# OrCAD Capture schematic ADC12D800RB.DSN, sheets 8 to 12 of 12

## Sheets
8 PLL: size B; block B3
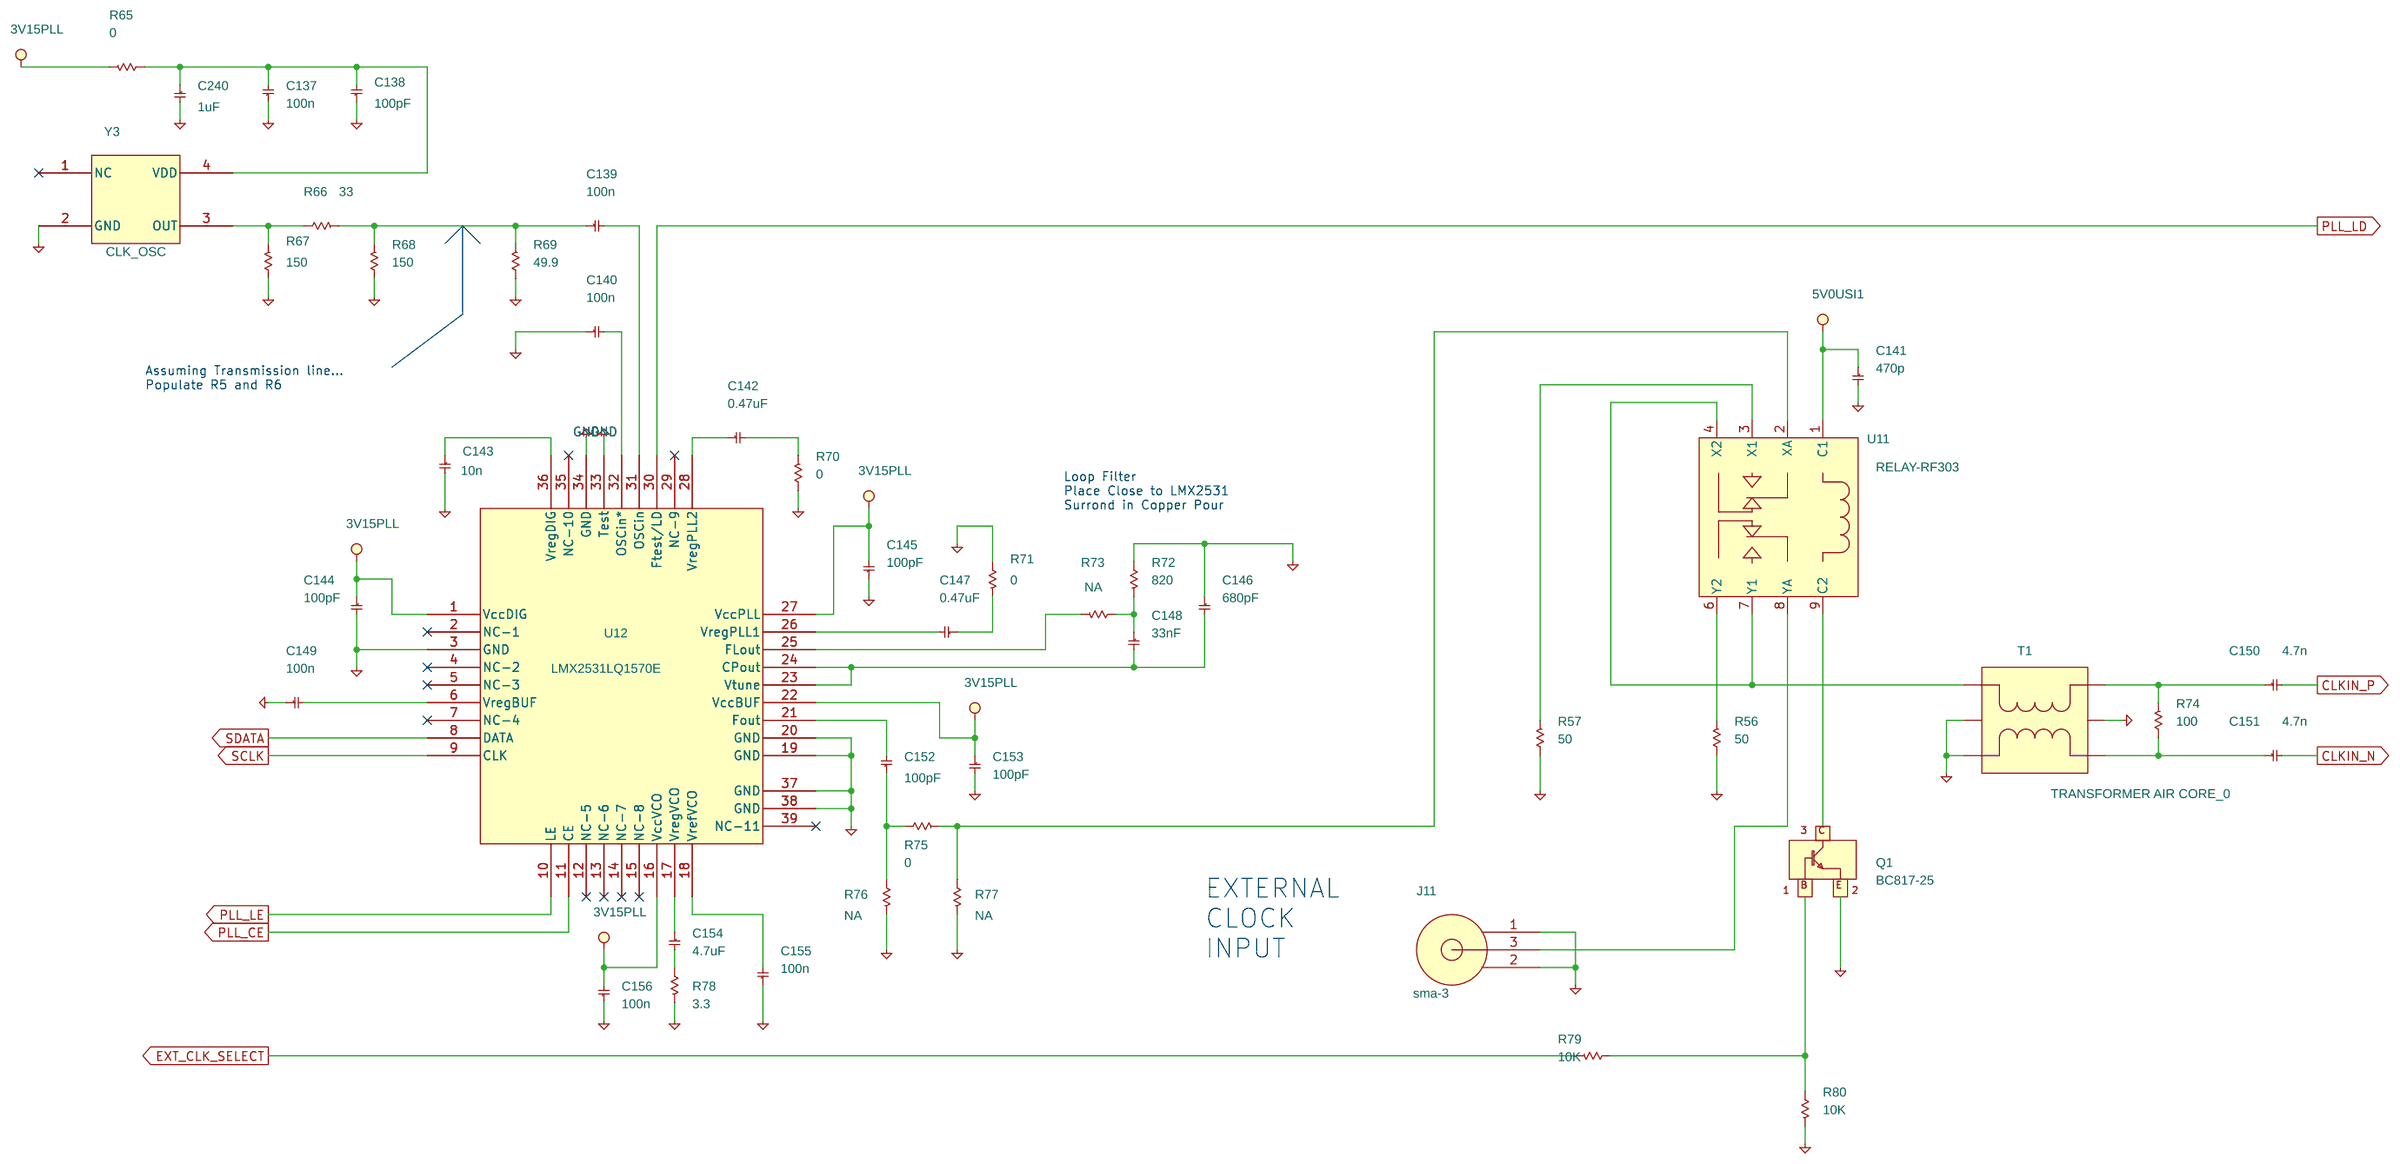
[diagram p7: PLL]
9 FPGA1: size C; block B7
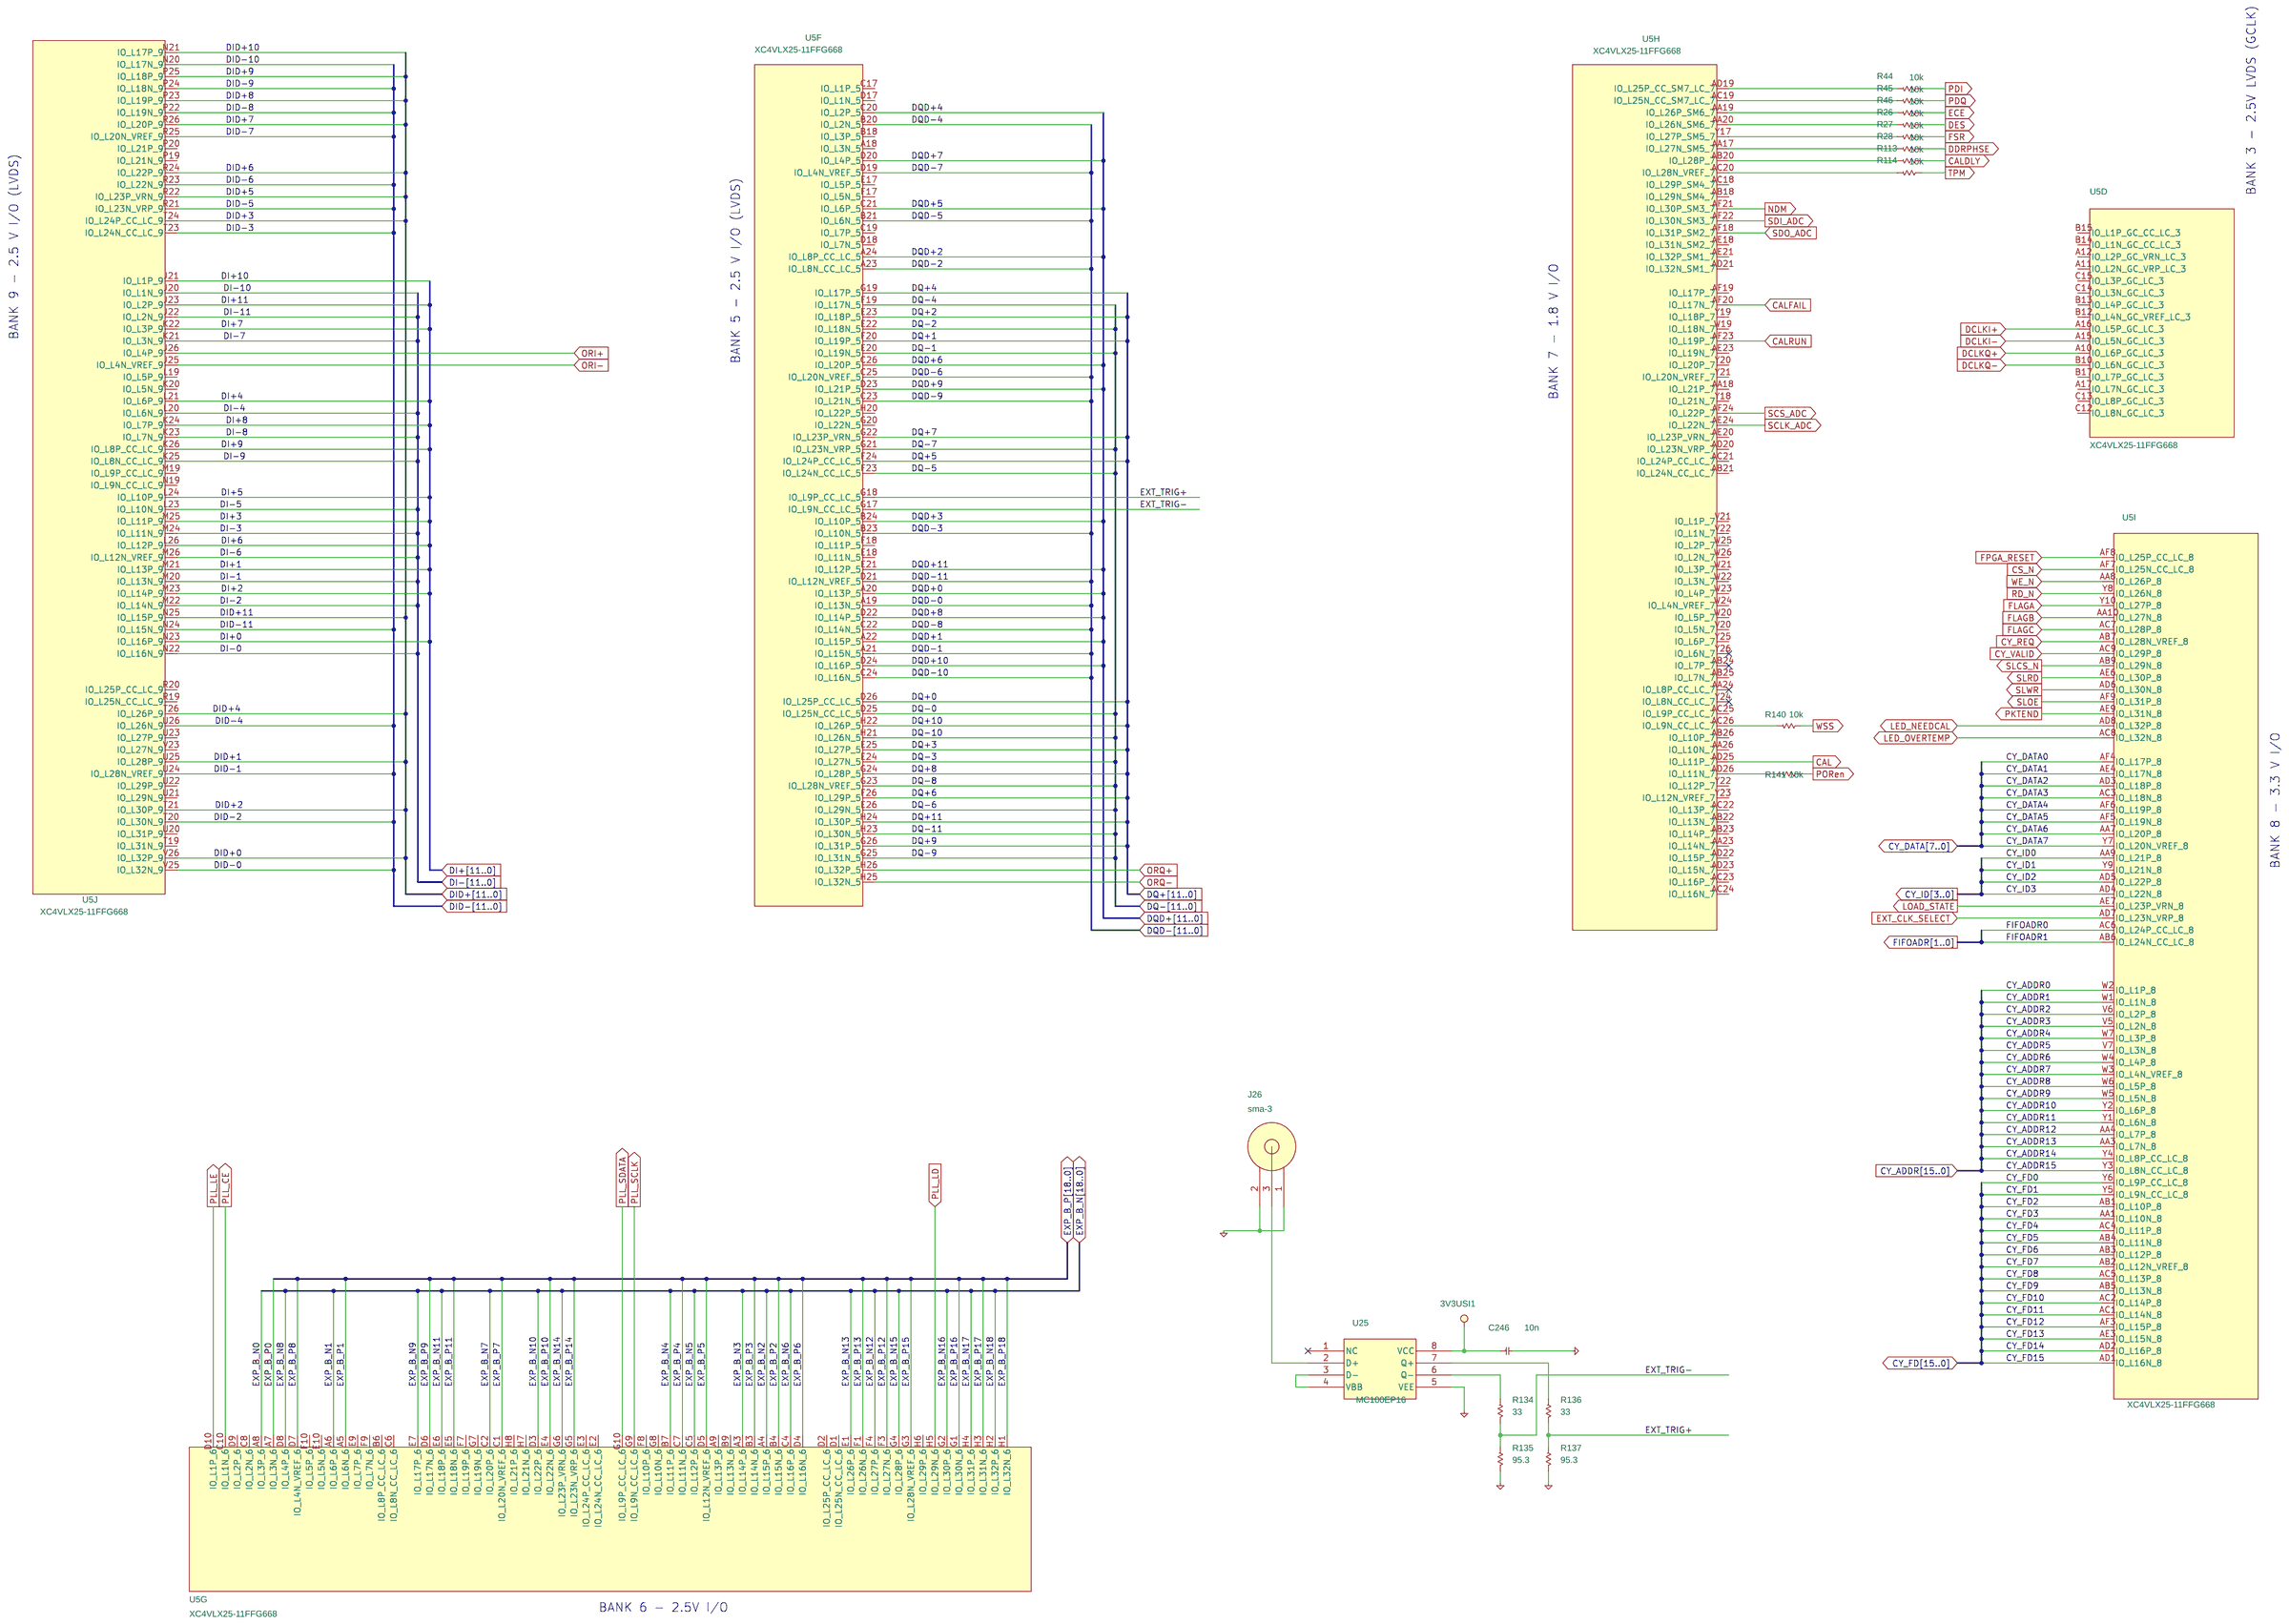
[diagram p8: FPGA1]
10 FPGA2: size C; block B7
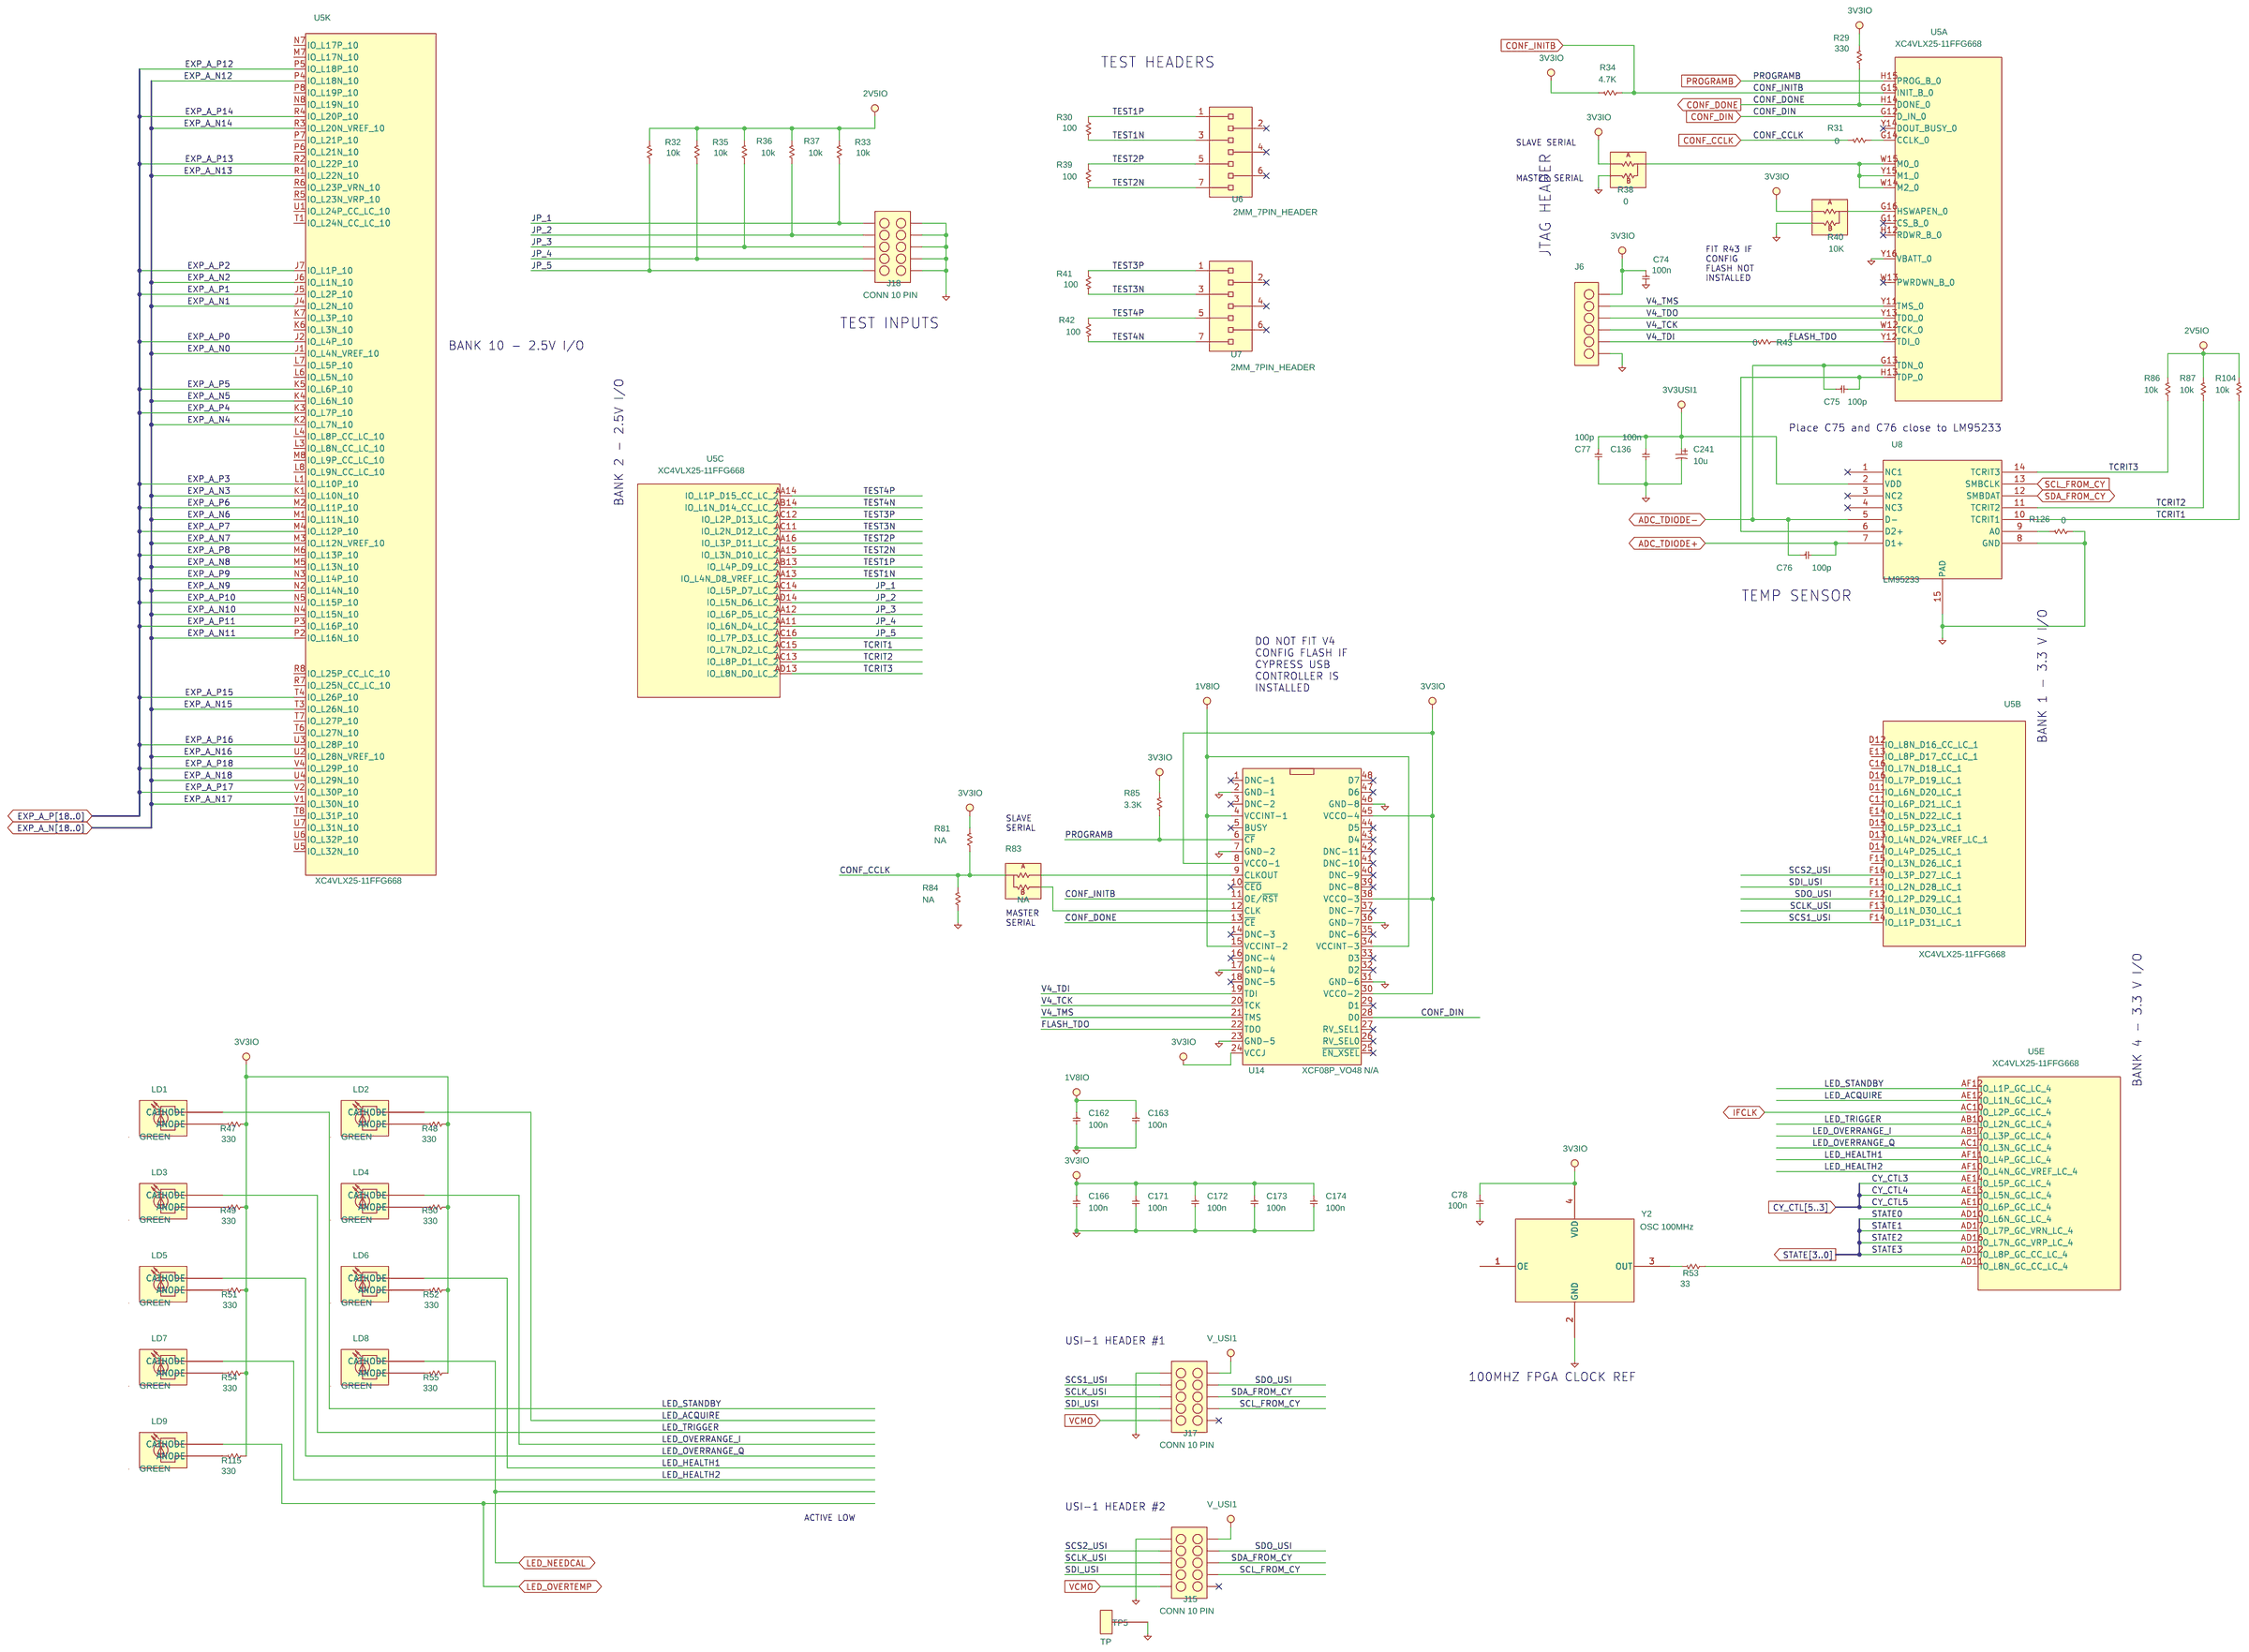
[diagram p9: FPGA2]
11 FPGA3: size C; block B7
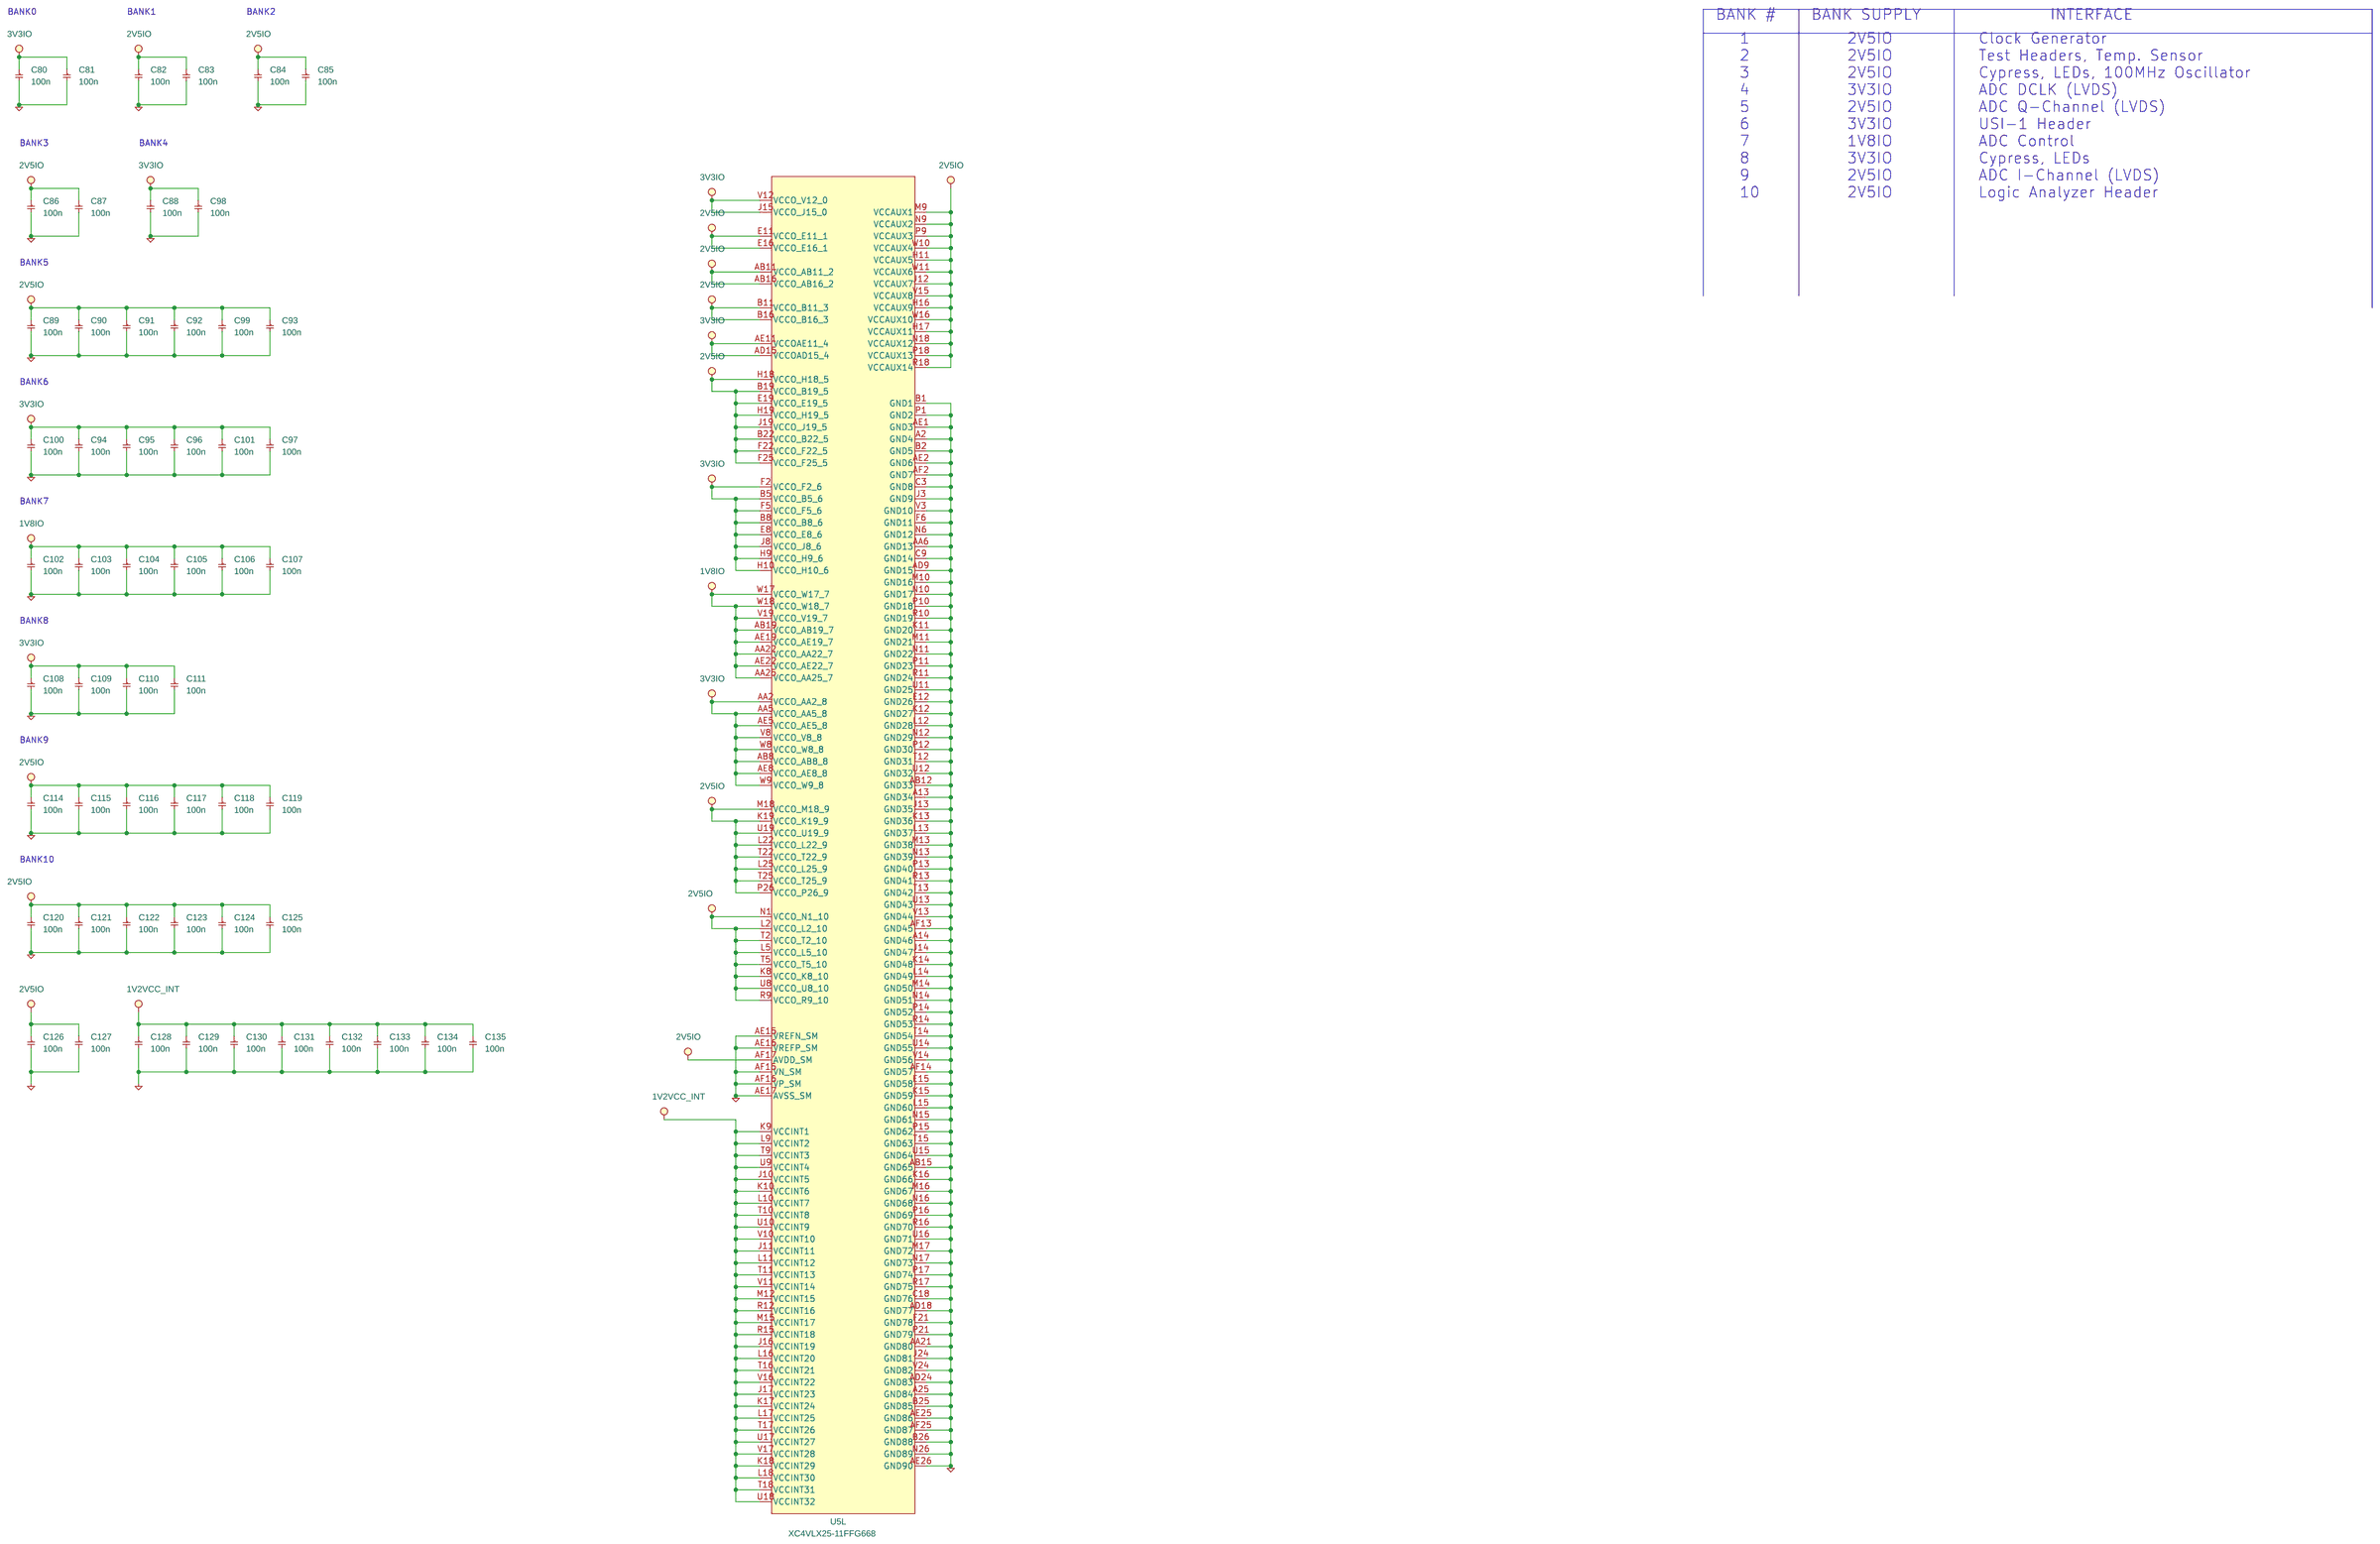
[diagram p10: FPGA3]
12 Front End: size C; block B6
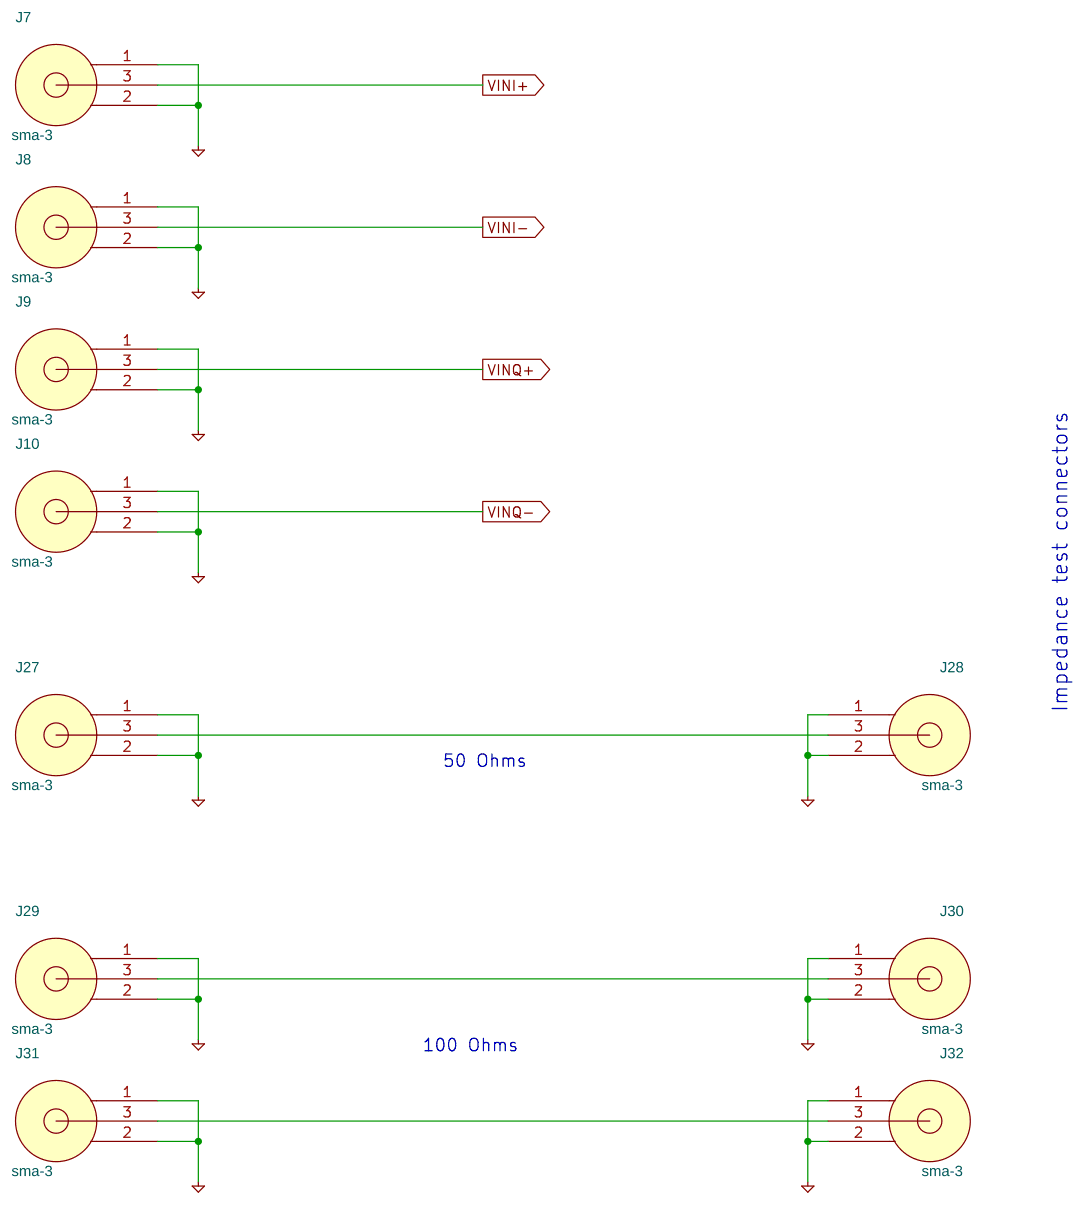
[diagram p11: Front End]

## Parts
sheet FPGA1
C246  10n  [c0402]
J26  sma-3  [RF_SMA_END_LAUNCH]
R26  10k  [r0603]
R27  10k  [r0603]
R28  10k  [r0603]
R44  10k  [r0603]
R45  10k  [r0603]
R46  10k  [r0603]
R113  10k  [r0603]
R114  10k  [r0603]
R134  33  [r0603]
R135  95.3  [r0603]
R136  33  [r0603]
R137  95.3  [r0603]
R140  10k  [r0603]
R141  10k  [r0603]
U25  MC100EP16  [TSSOP8_65M_WG4P9_L3]
sheet FPGA2
C74  100n  [c0603]
C75  100p  [c0402]
C76  100p  [c0402]
C77  100p  [c0402]
C78  100n  [c0603]
C136  100n  [c0603]
C162  100n  [c0603]
C163  100n  [c0603]
C166  100n  [c0603]
C171  100n  [c0603]
C172  100n  [c0603]
C173  100n  [c0603]
C174  100n  [c0603]
C241  10u  [c0805]
J6  CONN 6 PIN SINGLE ROW  [SHDR6X1]
J15  CONN 10 PIN  [th_10_hdr2x5_m_str_100]
J17  CONN 10 PIN  [th_10_hdr2x5_m_str_100]
J18  CONN 10 PIN  [th_10_hdr2x5_m_str_100]
LD1  GREEN  [r1206]
LD2  GREEN  [r1206]
LD3  GREEN  [r1206]
LD4  GREEN  [r1206]
LD5  GREEN  [r1206]
LD6  GREEN  [r1206]
LD7  GREEN  [r1206]
LD8  GREEN  [r1206]
LD9  GREEN  [r1206]
R29  330  [r0603]
R30  100  [r0603]
R31  0  [r0603]
R32  10k  [r0603]
R33  10k  [r0603]
R34  4.7K  [r0603]
R35  10k  [r0603]
R36  10k  [r0603]
R37  10k  [r0603]
R38  0  [0603_TRIPAD]
R39  100  [r0603]
R40  10K  [0603_TRIPAD]
R41  100  [r0603]
R42  100  [r0603]
R43  0  [r0603]
R47  330  [r0603]
R48  330  [r0603]
R49  330  [r0603]
R50  330  [r0603]
R51  330  [r0603]
R52  330  [r0603]
R53  33  [r0603]
R54  330  [r0603]
R55  330  [r0603]
R81  NA  [r0603]
R83  NA  [0603_TRIPAD]
R84  NA  [r0603]
R85  3.3K  [r0603]
R86  10k  [r0603]
R87  10k  [r0603]
R104  10k  [r0603]
R115  330  [r0603]
R126  0  [r0603]
TP5  TP  [tp40]
U5  XC4VLX25-11FFG668  [bga_668_27x27_1p0]  (sections A,B,C,D,E,F,G,H,I,J,K,L)
U6  2MM_7PIN_HEADER  [sm_7pin_ftr]
U7  2MM_7PIN_HEADER  [sm_7pin_ftr]
U8  LM95233  [LLP14_p5mm_4x4_ep]
U14  XCF08P_VO48 N/A  [TSSOP48_50M_WG20_L12]
Y2  OSC 100MHz  [osc_100m_5x7]
sheet FPGA3
C80  100n  [c0402]
C81  100n  [c0402]
C82  100n  [c0402]
C83  100n  [c0402]
C84  100n  [c0402]
C85  100n  [c0402]
C86  100n  [c0402]
C87  100n  [c0402]
C88  100n  [c0402]
C89  100n  [c0402]
C90  100n  [c0402]
C91  100n  [c0402]
C92  100n  [c0402]
C93  100n  [c0402]
C94  100n  [c0402]
C95  100n  [c0402]
C96  100n  [c0402]
C97  100n  [c0402]
C98  100n  [c0402]
C99  100n  [c0402]
C100  100n  [c0402]
C101  100n  [c0402]
C102  100n  [c0402]
C103  100n  [c0402]
C104  100n  [c0402]
C105  100n  [c0402]
C106  100n  [c0402]
C107  100n  [c0402]
C108  100n  [c0402]
C109  100n  [c0402]
C110  100n  [c0402]
C111  100n  [c0402]
C114  100n  [c0402]
C115  100n  [c0402]
C116  100n  [c0402]
C117  100n  [c0402]
C118  100n  [c0402]
C119  100n  [c0402]
C120  100n  [c0402]
C121  100n  [c0402]
C122  100n  [c0402]
C123  100n  [c0402]
C124  100n  [c0402]
C125  100n  [c0402]
C126  100n  [c0402]
C127  100n  [c0402]
C128  100n  [c0402]
C129  100n  [c0402]
C130  100n  [c0402]
C131  100n  [c0402]
C132  100n  [c0402]
C133  100n  [c0402]
C134  100n  [c0402]
C135  100n  [c0402]
sheet Front End
J7  sma-3  [RF_SMA_END_LAUNCH]
J8  sma-3  [RF_SMA_END_LAUNCH]
J9  sma-3  [RF_SMA_END_LAUNCH]
J10  sma-3  [RF_SMA_END_LAUNCH]
J27  sma-3  [RF_SMA_END_LAUNCH]
J28  sma-3  [RF_SMA_END_LAUNCH]
J29  sma-3  [RF_SMA_END_LAUNCH]
J30  sma-3  [RF_SMA_END_LAUNCH]
J31  sma-3  [RF_SMA_END_LAUNCH]
J32  sma-3  [RF_SMA_END_LAUNCH]
sheet PLL
C137  100n  [c0603]
C138  100pF  [c0603]
C139  100n  [c0603]
C140  100n  [c0603]
C141  470p  [c0603]
C142  0.47uF  [c0603]
C143  10n  [c0603]
C144  100pF  [c0603]
C145  100pF  [c0603]
C146  680pF  [c0603]
C147  0.47uF  [c0603]
C148  33nF  [c0603]
C149  100n  [c0603]
C150  4.7n  [c0402_no_ss]
C151  4.7n  [c0402_no_ss]
C152  100pF  [c0402_no_ss]
C153  100pF  [c0603]
C154  4.7uF  [c0603]
C155  100n  [c0603]
C156  100n  [c0603]
C240  1uF  [c0603]
J11  sma-3  [RF_SMA_END_LAUNCH]
Q1  BC817-25  [SOT-23]
R56  50  [r0402_no_ss]
R57  50  [r0402_no_ss]
R65  0  [r0603]
R66  33  [r0603]
R67  150  [r0603]
R68  150  [r0603]
R69  49.9  [r0603]
R70  0  [r0603]
R71  0  [r0603]
R72  820  [r0603]
R73  NA  [r0603]
R74  100  [r0402_no_ss]
R75  0  [r0402_no_ss]
R76  NA  [r0402_no_ss]
R77  NA  [r0402_no_ss]
R78  3.3  [r0603]
R79  10K  [r0603]
R80  10K  [r0603]
T1  TRANSFORMER AIR CORE_0  [soic6_026_wg049_L079]
U11  RELAY-RF303  [RELAY_RF303]
U12  LMX2531LQ1570E  [LLP39_p5mm_6x6]
Y3  CLK_OSC  [SOGP200_4_WGP280]

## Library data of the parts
C80-C111 C114-C135 C246 = C-NON-POL: Capacitor, SMT 0402, MLC, X5R, 10%, 10V; Distributor: Digikey; Distributor Part Number: PCC2146TR-ND; Manufacturer: Panasonic; Manufacturer Part Number: ECJ-0EB1A104K
J7-J11 J26-J32 = sma-3_0
R26-R28 R31 R44-R46 R65 R81 R84 R113 R114 R126 R140 R141 = RESISTOR_v2: RES 0 OHM 1/10W 5% 0603 SMD; Distributor: Digikey; Distributor Part Number: P0.0GTR-ND; Manufacturer: Panasonic; Manufacturer Part Number: ERJ-3GEY0R00V
R32 R33 R35-R37 R70 R71 R79 R80 R134-R137 = RESISTOR_v2: RES 10K OHM 1/10W 5% 0603 SMD; Distributor: Digikey; Distributor Part Number: P10KGTR-ND; Manufacturer: Panasonic; Manufacturer Part Number: ERJ-3GEYJ103V
U25 = MC10EP16: Distributor: Newark; Distributor Part Number: 45J0940; Manufacturer: On Semiconductor; Manufacturer Part Number: MC100EP16DTR2G
C74-C78 C136 C137 C139 C140 C149 C155 C156 C162 C163 C166 C171-C174 = C-NON-POL: Capacitor, SMT 0603, MLC, X7R, 10%, 16V; Distributor: Digikey; Distributor Part Number: PCC1762TR-ND; Manufacturer: Panasonic; Manufacturer Part Number: ECJ-1VB1C104K
C241 = C-POLARISED: CAP POL TDK 10UF X5R; Distributor: Digikey; Distributor Part Number: 445-1363-2-ND; Manufacturer: TDK; Manufacturer Part Number: C2012X5R0J1061M
J6 = CONN_6_PIN_SINGLE_ROW: HEADER 6X1 0.1" SP MALE STR; Distributor: Digikey; Distributor Part Number: S1012-36-ND; Manufacturer: Sullins; Manufacturer Part Number: PTC36SAAN
J15 J17 J18 = CONN_10_PIN_2mm_SMT_DUAL_ROW: CONN HEADER .100 DUAL STR 72POS; Distributor: Digikey; Distributor Part Number: S2012-36-ND; Manufacturer: Sullins; Manufacturer Part Number: PTC36DAAN
LD1-LD4 LD6 LD8 LD9 = LED_SNGLE_PANEL: LED 2X3MM 565NM GRN WTR CLR SMD; Distributor: Digikey; Distributor Part Number: 67-1357-1-ND; Manufacturer: Lumex; Manufacturer Part Number: SML-LX1206GC-TR
LD5 LD7 = LED_SNGLE_PANEL: LED 2X3MM 635NM RED WTR CLR SMD; Distributor: Digikey; Distributor Part Number: 67-1356-2-ND; Manufacturer: Lumex; Manufacturer Part Number: SML-LX1206IC-TR
R29 R47-R52 R54 R55 R115 = RESISTOR_v2: RES 330 OHM 1/10W 5% 0603 SMD; Distributor: Digikey; Distributor Part Number: P330GTR-ND; Manufacturer: Panasonic; Manufacturer Part Number: ERJ-3GEYJ331V
R30 R39 R41 R42 = RESISTOR_v2: RES 100 OHM 1/10W 5% 0603 SMD; Distributor: Digikey; Distributor Part Number: P100GTR-ND; Manufacturer: Panasonic; Manufacturer Part Number: ERJ-3GEYJ101V
R34 R43 = RESISTOR_v2: RES 4.7K OHM 1/10W 5% 0603 SMD; Distributor: Digikey; Distributor Part Number: P4.7KGTR-ND; Manufacturer: Panasonic; Manufacturer Part Number: ERJ-3GEYJ472V
R38 R83 = RESISTOR_TRIPAD: RES 0 OHM 1/10W 5% 0603 SMD; Distributor: Digikey; Distributor Part Number: P0.0GTR-ND; Manufacturer: Panasonic; Manufacturer Part Number: ERJ-3GEY0R00V
R40 = RESISTOR_TRIPAD: RES 10K OHM 1/10W 5% 0603 SMD; Distributor: Digikey; Distributor Part Number: P10KGTR-ND; Manufacturer: Panasonic; Manufacturer Part Number: ERJ-3GEYJ103V
R53 = RESISTOR_v2: RES 22.1K OHM 1/10W 1% 0603 SMD; Distributor: Digikey; Distributor Part Number: P22.1KHTR-ND; Manufacturer: Panasonic; Manufacturer Part Number: ERJ-3EKF2212V
R85-R87 R104 = RESISTOR_v2: RES 3.3K OHM 1/10W 5% 0603 SMD; Distributor: Digikey; Distributor Part Number: P3.3KGTR-ND; Manufacturer: Panasonic; Manufacturer Part Number: ERJ-3GEYJ332V
TP5 = TEST_POINT: TESTPOINT; Distributor: N/A; Distributor Part Number: N/A; Manufacturer: N/A; Manufacturer Part Number: N/A
U5 = XC4VLX25-11FFG668__3: FPGA VIRTEX-4 FG668 -11; Distributor: NuHorizons; Manufacturer: Xilinx
U6 U7 = 2MM_7PIN_HEADER: CONN HEADER 7POS SNGL 2MM SMD; Distributor: Digikey; Distributor Part Number: SAM1170-07-ND; Manufacturer: Samtec; Manufacturer Part Number: TMM-107-01-S-S-SM
U8 = LM95233
U14 = XCF08P_VO48_1: Xilinx Configuration Flash ROM (8Mb) JTAG; Manufacturer: Xilinx; Manufacturer Part Number: XCF08P VO48 C
Y2 = OSC-SM: OSC CLOCK 100.0000 MHZ 3.3V SMD; Distributor: Pletronics; Distributor Part Number: SM7745DSV-100.00M; Manufacturer: Pletronics; Manufacturer Part Number: SM7745DSV-100.00M
C138 C144 C145 C153 C154 = C-NON-POL: Capacitor, SMT 0603, MLC, NPO, 5%, 50V; Distributor: Digikey; Distributor Part Number: PCC101ACVTR-ND; Manufacturer: Panasonic; Manufacturer Part Number: ECJ-1VC1H101J
C141 = C-NON-POL: Capacitor, SMT 0603, MLC, NPO, 5%, 50V; Distributor: Digikey; Distributor Part Number: PCC2147CT-ND; Manufacturer: Panasonic; Manufacturer Part Number: ECJ-1VC1H471J
C142 C147 = C-NON-POL: Capacitor, SMT 0603, MLC, X7R, 10%, 16V; Distributor: Digikey; Distributor Part Number: 399-4922-2-ND; Manufacturer: Kemet; Manufacturer Part Number: C0603C474K4RACTU
C143 = C-NON-POL: Capacitor, SMT 0603, MLC, X7R, 10%, 16V; Distributor: Digikey; Distributor Part Number: PCC1750TR-ND; Manufacturer: Panasonic; Manufacturer Part Number: ECJ-1VB1C103K
C146 = C-NON-POL: Capacitor, SMT 0603, MLC, NPO, 5%, 50V; Distributor: Digikey; Distributor Part Number: PCC221ACVTR-ND; Manufacturer: Panasonic; Manufacturer Part Number: ECJ-1VC1H221J
C148 = C-NON-POL: Capacitor, SMT 0603, MLC, X7R, 10%, 16V; Distributor: Digikey; Distributor Part Number: 490-3292-1-ND; Manufacturer: MuRata; Manufacturer Part Number: GRM188R71C154KA01D
C150 C151 = C-NON-POL: Capacitor, SMT 0402, MLC, X7R, 10%, 25V; Distributor: Digikey; Distributor Part Number: PCC472BQTR-ND; Manufacturer: Panasonic; Manufacturer Part Number: ECJ-0EB1E472K
C152 = C-NON-POL: Capacitor, SMT 0402, MLC, X7R, 5%, 50V; Distributor: Digikey; Distributor Part Number: PCC101CQTR-ND; Manufacturer: Panasonic; Manufacturer Part Number: ECJ-0EC1H101J
C240 = C-NON-POL: Capacitor, SMT 0603, MLC, X5R, 10%, 16V; Distributor: Digikey; Distributor Part Number: PCC2224TR-ND; Manufacturer: Panasonic; Manufacturer Part Number: ECJ-1VB1C105K
Q1 = TRANSISTOR_NPN_BC817_SMD: TRANS NPN GP 500MA 45V SOT23; Distributor: Digikey; Distributor Part Number: BC817-25LT1OSCT-ND; Manufacturer: ON Semiconductor; Manufacturer Part Number: BC817-25LT1
R56 R57 R74 = RESISTOR_v2: RES 100 OHM 1/16W 5% 0402 SMD; Distributor: Digikey; Distributor Part Number: P100JTR-ND; Manufacturer: Panasonic; Manufacturer Part Number: ERJ-2GEJ101X
R66 R78 = RESISTOR_v2: RES 18 OHM 1/10W 5% 0603 SMD; Distributor: Digikey; Distributor Part Number: P18GTR-ND; Manufacturer: Panasonic; Manufacturer Part Number: ERJ-3GEYJ180V
R67 = RESISTOR_v2: RES 680 OHM 1/10W 5% 0603 SMD; Distributor: Digikey; Distributor Part Number: P680GTR-ND; Manufacturer: Panasonic; Manufacturer Part Number: ERJ-3GEYJ681V
R68 = RESISTOR_v2: RES 270 OHM 1/10W 5% 0603 SMD; Distributor: Digikey; Distributor Part Number: P270GTR-ND; Manufacturer: Panasonic; Manufacturer Part Number: ERJ-3GEYJ271V
R69 = RESISTOR_v2: RES 49.9 OHM 1/10W 1% 0603 SMD; Distributor: Digikey; Distributor Part Number: P49.9HCT-ND; Manufacturer: Panasonic; Manufacturer Part Number: ERJ-3EKF49R9V
R72 = RESISTOR_v2: RES 1K OHM 1/10W 5% 0603 SMD; Distributor: Digikey; Distributor Part Number: P1.0KGTR-ND; Manufacturer: Panasonic; Manufacturer Part Number: ERJ-3GEYJ102V
R73 = RESISTOR_v2: RES 2K7 OHM 1/10W 5% 0603 SMD; Distributor: Digikey; Distributor Part Number: P2.7KGTR-ND; Manufacturer: Panasonic; Manufacturer Part Number: ERJ-3GEYJ272V
R75-R77 = RESISTOR_v2: RES 0 OHM 1/16W 5% 0402 SMD; Distributor: Digikey; Distributor Part Number: P0.0JTR-ND; Manufacturer: Panasonic; Manufacturer Part Number: ERJ-2GE0R00X
T1 = TRANSFORMER_AIR_CORE_0: ANAREN XINGER FO-3 RF TRANSFORMER SMT; Manufacturer: Anaren; Manufacturer Part Number: FO-3
U11 = RELAY-RF303: RF RELAY DPDT; Distributor: Avnet; Manufacturer: Teledyne; Manufacturer Part Number: RF303-5
U12 = LMX2531LQ1500E
Y3 = Oscillator_4smd_0: Distributor: Pletronics; Distributor Part Number: SM7744HV-60.0M; Manufacturer: Pletronics; Manufacturer Part Number: SM7744HV-60.0M

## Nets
1V2VCC_INT: C128.1 C129.1 C130.1 C131.1 C132.1 C133.1 C134.1 C135.1 U5.J10(VCCINT5) U5.J11(VCCINT11) U5.J16(VCCINT19) U5.J17(VCCINT23) U5.K9(VCCINT1) U5.K10(VCCINT6) U5.K17(VCCINT24) U5.K18(VCCINT29) U5.L9(VCCINT2) U5.L10(VCCINT7) U5.L11(VCCINT12) U5.L16(VCCINT20) U5.L17(VCCINT25) U5.L18(VCCINT30) U5.M12(VCCINT15) U5.M15(VCCINT17) U5.R12(VCCINT16) U5.R15(VCCINT18) U5.T9(VCCINT3) U5.T10(VCCINT8) U5.T11(VCCINT13) U5.T16(VCCINT21) U5.T17(VCCINT26) U5.T18(VCCINT31) U5.U9(VCCINT4) U5.U10(VCCINT9) U5.U17(VCCINT27) U5.U18(VCCINT32) U5.V10(VCCINT10) U5.V11(VCCINT14) U5.V16(VCCINT22) U5.V17(VCCINT28) ; also on sheet 5
1V8IO: C102.1 C103.1 C104.1 C105.1 C106.1 C107.1 C162.1 C163.1 U5.AA22(VCCO_AA22_7) U5.AA25(VCCO_AA25_7) U5.AB19(VCCO_AB19_7) U5.AE19(VCCO_AE19_7) U5.AE22(VCCO_AE22_7) U5.V19(VCCO_V19_7) U5.W17(VCCO_W17_7) U5.W18(VCCO_W18_7) U14.4(VCCINT-1) U14.15(VCCINT-2) U14.34(VCCINT-3) ; also on sheet 3 5
2V5IO: C82.1 C83.1 C84.1 C85.1 C86.1 C87.1 C89.1 C90.1 C91.1 C92.1 C93.1 C99.1 C114.1 C115.1 C116.1 C117.1 C118.1 C119.1 C120.1 C121.1 C122.1 C123.1 C124.1 C125.1 C126.1 C127.1 R32.1 R33.1 R35.1 R36.1 R37.1 R86.1 R87.1 R104.1 U5.AB11(VCCO_AB11_2) U5.AB16(VCCO_AB16_2) U5.AF17(AVDD_SM) U5.B11(VCCO_B11_3) U5.B16(VCCO_B16_3) U5.B19(VCCO_B19_5) U5.B22(VCCO_B22_5) U5.E11(VCCO_E11_1) U5.E16(VCCO_E16_1) U5.E19(VCCO_E19_5) U5.F22(VCCO_F22_5) U5.F25(VCCO_F25_5) U5.H11(VCCAUX5) U5.H16(VCCAUX9) U5.H17(VCCAUX11) U5.H18(VCCO_H18_5) U5.H19(VCCO_H19_5) U5.J12(VCCAUX7) U5.J19(VCCO_J19_5) U5.K8(VCCO_K8_10) U5.K19(VCCO_K19_9) U5.L2(VCCO_L2_10) U5.L5(VCCO_L5_10) U5.L22(VCCO_L22_9) U5.L25(VCCO_L25_9) U5.M9(VCCAUX1) U5.M18(VCCO_M18_9) U5.N1(VCCO_N1_10) U5.N9(VCCAUX2) U5.N18(VCCAUX12) U5.P9(VCCAUX3) U5.P18(VCCAUX13) U5.P26(VCCO_P26_9) U5.R9(VCCO_R9_10) U5.R18(VCCAUX14) U5.T2(VCCO_T2_10) U5.T5(VCCO_T5_10) U5.T22(VCCO_T22_9) U5.T25(VCCO_T25_9) U5.U8(VCCO_U8_10) U5.U19(VCCO_U19_9) U5.V15(VCCAUX8) U5.W10(VCCAUX4) U5.W11(VCCAUX6) U5.W16(VCCAUX10) ; also on sheet 5
3V3IO: C74.1 C78.1 C80.1 C81.1 C88.1 C94.1 C95.1 C96.1 C97.1 C98.1 C100.1 C101.1 C108.1 C109.1 C110.1 C111.1 C166.1 C171.1 C172.1 C173.1 C174.1 J6.1 R29.1 R34.1 R38.1 R40.1 R47.2 R48.2 R49.2 R50.2 R51.2 R52.2 R54.2 R55.2 R81.1 R85.1 R115.2 U5.AA2(VCCO_AA2_8) U5.AA5(VCCO_AA5_8) U5.AB8(VCCO_AB8_8) U5.AD15(VCCOAD15_4) U5.AE5(VCCO_AE5_8) U5.AE8(VCCO_AE8_8) U5.AE11(VCCOAE11_4) U5.B5(VCCO_B5_6) U5.B8(VCCO_B8_6) U5.E8(VCCO_E8_6) U5.F2(VCCO_F2_6) U5.F5(VCCO_F5_6) U5.H9(VCCO_H9_6) U5.H10(VCCO_H10_6) U5.J8(VCCO_J8_6) U5.J15(VCCO_J15_0) U5.V8(VCCO_V8_8) U5.V12(VCCO_V12_0) U5.W8(VCCO_W8_8) U5.W9(VCCO_W9_8) U14.8(VCCO-1) U14.24(VCCJ) U14.30(VCCO-2) U14.38(VCCO-3) U14.45(VCCO-4) Y2.4(VDD) ; also on sheet 5
3V3USI1: C77.1 C136.1 C241.1(POS) C246.1 U8.2(VDD) U25.8(VCC) ; also on sheet 3 5
3V15PLL: C144.1 C145.2 C153.1 C156.2 R65.1 U12.1(VccDIG) U12.16(VccVCO) U12.22(VccBUF) U12.27(VccPLL) ; also on sheet 6
5V0USI1: C141.1 U11.1(C1) ; also on sheet 5
B7/V4_TCK: J6.4 U5.W12(TCK_0) U14.20(TCK)
B7/V4_TDI: J6.5 R43.1 U14.19(TDI)
B7/V4_TDO: J6.3 U5.Y13(TDO_0)
B7/V4_TMS: J6.2 U5.Y11(TMS_0) U14.21(TMS)
GND: C74.2 C77.2 C78.2 C80.2 C81.2 C82.2 C83.2 C84.2 C85.2 C86.2 C87.2 C88.2 C89.2 C90.2 C91.2 C92.2 C93.2 C94.2 C95.2 C96.2 C97.2 C98.2 C99.2 C100.2 C101.2 C102.2 C103.2 C104.2 C105.2 C106.2 C107.2 C108.2 C109.2 C110.2 C111.2 C114.2 C115.2 C116.2 C117.2 C118.2 C119.2 C120.2 C121.2 C122.2 C123.2 C124.2 C125.2 C126.2 C127.2 C128.2 C129.2 C130.2 C131.2 C132.2 C133.2 C134.2 C135.2 C136.2 C137.1 C138.1 C140.1 C141.2 C143.2 C144.2 C145.1 C146.1 C149.1 C153.2 C155.1 C156.1 C162.2 C163.2 C166.2 C171.2 C172.2 C173.2 C174.2 C240.2 C241.2(NEG) C246.2 J6.6 J7.1 J7.2 J8.1 J8.2 J9.1 J9.2 J10.1 J10.2 J11.1 J11.2 J15.1 J17.1 J18.2 J18.4 J18.6 J18.8 J18.10 J26.1 J26.2 J27.1 J27.2 J28.1 J28.2 J29.1 J29.2 J30.1 J30.2 J31.1 J31.2 J32.1 J32.2 Q1.2(EMITTER) R38.3 R40.3 R56.2 R57.2 R67.2 R68.2 R69.2 R70.2 R71.2 R72.2 R76.1 R77.1 R78.1 R80.1 R84.2 R126.2 R135.2 R137.2 T1.1 T1.3 T1.5 TP5.1 U5.A2(GND4) U5.A13(GND34) U5.A14(GND46) U5.A25(GND84) U5.AA6(GND13) U5.AA21(GND80) U5.AB12(GND33) U5.AB15(GND65) U5.AD9(GND15) U5.AD18(GND77) U5.AD24(GND83) U5.AE1(GND3) U5.AE2(GND6) U5.AE15(VREFN_SM) U5.AE16(VREFP_SM) U5.AE17(AVSS_SM) U5.AE25(GND86) U5.AE26(GND90) U5.AF2(GND7) U5.AF13(GND45) U5.AF14(GND57) U5.AF15(VN_SM) U5.AF16(VP_SM) U5.AF25(GND87) U5.B1(GND1) U5.B2(GND5) U5.B25(GND85) U5.B26(GND88) U5.C3(GND8) U5.C9(GND14) U5.C18(GND76) U5.E12(GND26) U5.E15(GND58) U5.F6(GND11) U5.F21(GND78) U5.J3(GND9) U5.J13(GND35) U5.J14(GND47) U5.J24(GND81) U5.K11(GND20) U5.K12(GND27) U5.K13(GND36) U5.K14(GND48) U5.K15(GND59) U5.K16(GND66) U5.L12(GND28) U5.L13(GND37) U5.L14(GND49) U5.L15(GND60) U5.M10(GND16) U5.M11(GND21) U5.M13(GND38) U5.M14(GND50) U5.M16(GND67) U5.M17(GND72) U5.N6(GND12) U5.N10(GND17) U5.N11(GND22) U5.N12(GND29) U5.N13(GND39) U5.N14(GND51) U5.N15(GND61) U5.N16(GND68) U5.N17(GND73) U5.N26(GND89) U5.P1(GND2) U5.P10(GND18) U5.P11(GND23) U5.P12(GND30) U5.P13(GND40) U5.P14(GND52) U5.P15(GND62) U5.P16(GND69) U5.P17(GND74) U5.P21(GND79) U5.R10(GND19) U5.R11(GND24) U5.R13(GND41) U5.R14(GND53) U5.R16(GND70) U5.R17(GND75) U5.T12(GND31) U5.T13(GND42) U5.T14(GND54) U5.T15(GND63) U5.U11(GND25) U5.U12(GND32) U5.U13(GND43) U5.U14(GND55) U5.U15(GND64) U5.U16(GND71) U5.V3(GND10) U5.V13(GND44) U5.V14(GND56) U5.V24(GND82) U5.Y16(VBATT_0) U8.8(GND) U8.15(PAD) U12.3(GND) U12.19(GND) U12.20(GND) U12.33(Test) U12.34(GND) U12.37(GND) U12.38(GND) U14.2(GND-1) U14.7(GND-2) U14.17(GND-4) U14.23(GND-5) U14.31(GND-6) U14.36(GND-7) U14.46(GND-8) U25.5(VEE) Y2.2(GND) Y3.2(GND) ; also on sheet 3 4 5 6 7
VINI+: J7.3 ; also on sheet 3
VINI-: J8.3 ; also on sheet 3
VINQ+: J9.3 ; also on sheet 3
VINQ-: J10.3 ; also on sheet 3
ADC_TDIODE+: C76.2 U8.7(D1+) ; also on sheet 3
ADC_TDIODE-: C75.1 C76.1 U5.G13(TDN_0) U8.5(D-) ; also on sheet 3
B7/EXT_TRIG+: R136.2 R137.1 U5.G18(IO_L9P_CC_LC_5)
B7/EXT_TRIG-: R134.2 R135.1 U5.G17(IO_L9N_CC_LC_5)
B7/FLASH_TDO: R43.2 U5.Y12(TDI_0) U14.22(TDO)
B7/JP_1: J18.1 R33.2 U5.AC14(IO_L5P_D7_LC_2)
B7/JP_2: J18.3 R37.2 U5.AD14(IO_L5N_D6_LC_2)
B7/JP_3: J18.5 R36.2 U5.AA12(IO_L6P_D5_LC_2)
B7/JP_4: J18.7 R35.2 U5.AA11(IO_L6N_D4_LC_2)
B7/JP_5: J18.9 R32.2 U5.AC16(IO_L7P_D3_LC_2)
B7/LED_ACQUIRE: LD2.2(CATHODE) U5.AE12(IO_L1N_GC_LC_4)
B7/LED_HEALTH1: LD6.2(CATHODE) U5.AF11(IO_L4P_GC_LC_4)
B7/LED_HEALTH2: LD7.2(CATHODE) U5.AF10(IO_L4N_GC_VREF_LC_4)
B7/LED_NEEDCAL: LD8.2(CATHODE) U5.AD8(IO_L32P_8)
B7/LED_OVERRANGE_I: LD4.2(CATHODE) U5.AB17(IO_L3P_GC_LC_4)
B7/LED_OVERRANGE_Q: LD5.2(CATHODE) U5.AC17(IO_L3N_GC_LC_4)
B7/LED_OVERTEMP: LD9.2(CATHODE) U5.AC8(IO_L32N_8)
B7/LED_STANDBY: LD1.2(CATHODE) U5.AF12(IO_L1P_GC_LC_4)
B7/LED_TRIGGER: LD3.2(CATHODE) U5.AB10(IO_L2N_GC_LC_4)
B7/SCLK_USI: J15.5 J17.5 U5.F13(IO_L1N_D30_LC_1)
B7/SCS1_USI: J17.3 U5.F14(IO_L1P_D31_LC_1)
B7/SCS2_USI: J15.3 U5.F16(IO_L3P_D27_LC_1)
B7/SDI_USI: J15.7 J17.7 U5.F11(IO_L2N_D28_LC_1)
B7/SDO_USI: J15.4 J17.4 U5.F12(IO_L2P_D29_LC_1)
B7/TCRIT1: R104.2 U5.AC15(IO_L7N_D2_LC_2) U8.10(TCRIT1)
B7/TCRIT2: R87.2 U5.AC13(IO_L8P_D1_LC_2) U8.11(TCRIT2)
B7/TCRIT3: R86.2 U5.AD13(IO_L8N_D0_LC_2) U8.14(TCRIT3)
B7/TEST1N: R30.1 U5.AA13(IO_L4N_D8_VREF_LC_2) U6.3
B7/TEST1P: R30.2 U5.AB13(IO_L4P_D9_LC_2) U6.1
B7/TEST2N: R39.1 U5.AA15(IO_L3N_D10_LC_2) U6.7
B7/TEST2P: R39.2 U5.AA16(IO_L3P_D11_LC_2) U6.5
B7/TEST3N: R41.1 U5.AC11(IO_L2N_D12_LC_2) U7.3
B7/TEST3P: R41.2 U5.AC12(IO_L2P_D13_LC_2) U7.1
B7/TEST4N: R42.1 U5.AB14(IO_L1N_D14_CC_LC_2) U7.7
B7/TEST4P: R42.2 U5.AA14(IO_L1P_D15_CC_LC_2) U7.5
CAL: U5.AD25(IO_L11P_7) ; also on sheet 3
CALDLY: R113.2 ; also on sheet 3
CALFAIL: U5.AF20(IO_L17N_7) ; also on sheet 3
CALRUN: U5.AF23(IO_L19P_7) ; also on sheet 3
CLKIN_N: C151.2 ; also on sheet 3
CLKIN_P: C150.2 ; also on sheet 3
CONF_CCLK: R31.1 R81.2 R83.2 R84.1 ; also on sheet 4
CONF_DIN: U5.G12(D_IN_0) U14.28(D0) ; also on sheet 4
CONF_DONE: R29.2 U5.H14(DONE_0) U14.13(~{CE}) ; also on sheet 4
CONF_INITB: R34.2 U5.G15(INIT_B_0) U14.11(OE/~{RST}) ; also on sheet 4
CS_N: U5.AF7(IO_L25N_CC_LC_8) ; also on sheet 4
CY_ADDR0: U5.W2(IO_L1P_8) ; also on sheet 4
CY_ADDR1: U5.W1(IO_L1N_8) ; also on sheet 4
CY_ADDR2: U5.V6(IO_L2P_8) ; also on sheet 4
CY_ADDR3: U5.V5(IO_L2N_8) ; also on sheet 4
CY_ADDR4: U5.W7(IO_L3P_8) ; also on sheet 4
CY_ADDR5: U5.V7(IO_L3N_8) ; also on sheet 4
CY_ADDR6: U5.W4(IO_L4P_8) ; also on sheet 4
CY_ADDR7: U5.W3(IO_L4N_VREF_8) ; also on sheet 4
CY_ADDR8: U5.W6(IO_L5P_8) ; also on sheet 4
CY_ADDR9: U5.W5(IO_L5N_8) ; also on sheet 4
CY_ADDR10: U5.Y2(IO_L6P_8) ; also on sheet 4
CY_ADDR11: U5.Y1(IO_L6N_8) ; also on sheet 4
CY_ADDR12: U5.AA4(IO_L7P_8) ; also on sheet 4
CY_ADDR13: U5.AA3(IO_L7N_8) ; also on sheet 4
CY_ADDR14: U5.Y4(IO_L8P_CC_LC_8) ; also on sheet 4
CY_ADDR15: U5.Y3(IO_L8N_CC_LC_8) ; also on sheet 4
CY_CTL3: U5.AE14(IO_L5P_GC_LC_4) ; also on sheet 4
CY_CTL4: U5.AE13(IO_L5N_GC_LC_4) ; also on sheet 4
CY_CTL5: U5.AE10(IO_L6P_GC_LC_4) ; also on sheet 4
CY_DATA0: U5.AF4(IO_L17P_8) ; also on sheet 4
CY_DATA1: U5.AE4(IO_L17N_8) ; also on sheet 4
CY_DATA2: U5.AD3(IO_L18P_8) ; also on sheet 4
CY_DATA3: U5.AC3(IO_L18N_8) ; also on sheet 4
CY_DATA4: U5.AF6(IO_L19P_8) ; also on sheet 4
CY_DATA5: U5.AF5(IO_L19N_8) ; also on sheet 4
CY_DATA6: U5.AA7(IO_L20P_8) ; also on sheet 4
CY_DATA7: U5.Y7(IO_L20N_VREF_8) ; also on sheet 4
CY_FD0: U5.Y6(IO_L9P_CC_LC_8) ; also on sheet 4
CY_FD1: U5.Y5(IO_L9N_CC_LC_8) ; also on sheet 4
CY_FD2: U5.AB1(IO_L10P_8) ; also on sheet 4
CY_FD3: U5.AA1(IO_L10N_8) ; also on sheet 4
CY_FD4: U5.AC4(IO_L11P_8) ; also on sheet 4
CY_FD5: U5.AB4(IO_L11N_8) ; also on sheet 4
CY_FD6: U5.AB3(IO_L12P_8) ; also on sheet 4
CY_FD7: U5.AB2(IO_L12N_VREF_8) ; also on sheet 4
CY_FD8: U5.AC5(IO_L13P_8) ; also on sheet 4
CY_FD9: U5.AB5(IO_L13N_8) ; also on sheet 4
CY_FD10: U5.AC2(IO_L14P_8) ; also on sheet 4
CY_FD11: U5.AC1(IO_L14N_8) ; also on sheet 4
CY_FD12: U5.AF3(IO_L15P_8) ; also on sheet 4
CY_FD13: U5.AE3(IO_L15N_8) ; also on sheet 4
CY_FD14: U5.AD2(IO_L16P_8) ; also on sheet 4
CY_FD15: U5.AD1(IO_L16N_8) ; also on sheet 4
CY_ID0: U5.AA9(IO_L21P_8) ; also on sheet 4
CY_ID1: U5.Y9(IO_L21N_8) ; also on sheet 4
CY_ID2: U5.AD5(IO_L22P_8) ; also on sheet 4
CY_ID3: U5.AD4(IO_L22N_8) ; also on sheet 4
CY_REQ: U5.AB7(IO_L28N_VREF_8) ; also on sheet 4
CY_VALID: U5.AC9(IO_L29P_8) ; also on sheet 4
DCLKI+: U5.A16(IO_L5P_GC_LC_3) ; also on sheet 3
DCLKI-: U5.A15(IO_L5N_GC_LC_3) ; also on sheet 3
DCLKQ+: U5.A10(IO_L6P_GC_LC_3) ; also on sheet 3
DCLKQ-: U5.B10(IO_L6N_GC_LC_3) ; also on sheet 3
DDRPHASE: R28.2 ; also on sheet 3
DES: R26.2 ; also on sheet 3
DI+0: U5.N23(IO_L16P_9) ; also on sheet 3
DI+1: U5.M21(IO_L13P_9) ; also on sheet 3
DI+2: U5.M23(IO_L14P_9) ; also on sheet 3
DI+3: U5.M25(IO_L11P_9) ; also on sheet 3
DI+4: U5.L21(IO_L6P_9) ; also on sheet 3
DI+5: U5.L24(IO_L10P_9) ; also on sheet 3
DI+6: U5.L26(IO_L12P_9) ; also on sheet 3
DI+7: U5.K22(IO_L3P_9) ; also on sheet 3
DI+8: U5.K24(IO_L7P_9) ; also on sheet 3
DI+9: U5.K26(IO_L8P_CC_LC_9) ; also on sheet 3
DI+10: U5.J21(IO_L1P_9) ; also on sheet 3
DI+11: U5.J23(IO_L2P_9) ; also on sheet 3
DI-0: U5.N22(IO_L16N_9) ; also on sheet 3
DI-1: U5.M20(IO_L13N_9) ; also on sheet 3
DI-2: U5.M22(IO_L14N_9) ; also on sheet 3
DI-3: U5.M24(IO_L11N_9) ; also on sheet 3
DI-4: U5.L20(IO_L6N_9) ; also on sheet 3
DI-5: U5.L23(IO_L10N_9) ; also on sheet 3
DI-6: U5.M26(IO_L12N_VREF_9) ; also on sheet 3
DI-7: U5.K21(IO_L3N_9) ; also on sheet 3
DI-8: U5.K23(IO_L7N_9) ; also on sheet 3
DI-9: U5.K25(IO_L8N_CC_LC_9) ; also on sheet 3
DI-10: U5.J20(IO_L1N_9) ; also on sheet 3
DI-11: U5.J22(IO_L2N_9) ; also on sheet 3
DID+0: U5.V26(IO_L32P_9) ; also on sheet 3
DID+1: U5.U25(IO_L28P_9) ; also on sheet 3
DID+2: U5.T21(IO_L30P_9) ; also on sheet 3
DID+3: U5.T24(IO_L24P_CC_LC_9) ; also on sheet 3
DID+4: U5.T26(IO_L26P_9) ; also on sheet 3
DID+5: U5.R22(IO_L23P_VRN_9) ; also on sheet 3
DID+6: U5.R24(IO_L22P_9) ; also on sheet 3
DID+7: U5.R26(IO_L20P_9) ; also on sheet 3
DID+8: U5.P23(IO_L19P_9) ; also on sheet 3
DID+9: U5.P25(IO_L18P_9) ; also on sheet 3
DID+10: U5.N21(IO_L17P_9) ; also on sheet 3
DID+11: U5.N25(IO_L15P_9) ; also on sheet 3
DID-0: U5.V25(IO_L32N_9) ; also on sheet 3
DID-1: U5.U24(IO_L28N_VREF_9) ; also on sheet 3
DID-2: U5.T20(IO_L30N_9) ; also on sheet 3
DID-3: U5.T23(IO_L24N_CC_LC_9) ; also on sheet 3
DID-4: U5.U26(IO_L26N_9) ; also on sheet 3
DID-5: U5.R21(IO_L23N_VRP_9) ; also on sheet 3
DID-6: U5.R23(IO_L22N_9) ; also on sheet 3
DID-7: U5.R25(IO_L20N_VREF_9) ; also on sheet 3
DID-8: U5.P22(IO_L19N_9) ; also on sheet 3
DID-9: U5.P24(IO_L18N_9) ; also on sheet 3
DID-10: U5.N20(IO_L17N_9) ; also on sheet 3
DID-11: U5.N24(IO_L15N_9) ; also on sheet 3
DQ+0: U5.D26(IO_L25P_CC_LC_5) ; also on sheet 3
DQ+1: U5.F20(IO_L19P_5) ; also on sheet 3
DQ+2: U5.E23(IO_L18P_5) ; also on sheet 3
DQ+3: U5.E25(IO_L27P_5) ; also on sheet 3
DQ+4: U5.G19(IO_L17P_5) ; also on sheet 3
DQ+5: U5.F24(IO_L24P_CC_LC_5) ; also on sheet 3
DQ+6: U5.F26(IO_L29P_5) ; also on sheet 3
DQ+7: U5.G22(IO_L23P_VRN_5) ; also on sheet 3
DQ+8: U5.G24(IO_L28P_5) ; also on sheet 3
DQ+9: U5.G26(IO_L31P_5) ; also on sheet 3
DQ+10: U5.H22(IO_L26P_5) ; also on sheet 3
DQ+11: U5.H24(IO_L30P_5) ; also on sheet 3
DQ-0: U5.D25(IO_L25N_CC_LC_5) ; also on sheet 3
DQ-1: U5.E20(IO_L19N_5) ; also on sheet 3
DQ-2: U5.E22(IO_L18N_5) ; also on sheet 3
DQ-3: U5.E24(IO_L27N_5) ; also on sheet 3
DQ-4: U5.F19(IO_L17N_5) ; also on sheet 3
DQ-5: U5.F23(IO_L24N_CC_LC_5) ; also on sheet 3
DQ-6: U5.E26(IO_L29N_5) ; also on sheet 3
DQ-7: U5.G21(IO_L23N_VRP_5) ; also on sheet 3
DQ-8: U5.G23(IO_L28N_VREF_5) ; also on sheet 3
DQ-9: U5.G25(IO_L31N_5) ; also on sheet 3
DQ-10: U5.H21(IO_L26N_5) ; also on sheet 3
DQ-11: U5.H23(IO_L30N_5) ; also on sheet 3
DQD+0: U5.A20(IO_L13P_5) ; also on sheet 3
DQD+1: U5.A22(IO_L15P_5) ; also on sheet 3
DQD+2: U5.A24(IO_L8P_CC_LC_5) ; also on sheet 3
DQD+3: U5.B24(IO_L10P_5) ; also on sheet 3
DQD+4: U5.C20(IO_L2P_5) ; also on sheet 3
DQD+5: U5.C21(IO_L6P_5) ; also on sheet 3
DQD+6: U5.C26(IO_L20P_5) ; also on sheet 3
DQD+7: U5.D20(IO_L4P_5) ; also on sheet 3
DQD+8: U5.D22(IO_L14P_5) ; also on sheet 3
DQD+9: U5.D23(IO_L21P_5) ; also on sheet 3
DQD+10: U5.D24(IO_L16P_5) ; also on sheet 3
DQD+11: U5.E21(IO_L12P_5) ; also on sheet 3
DQD-0: U5.A19(IO_L13N_5) ; also on sheet 3
DQD-1: U5.A21(IO_L15N_5) ; also on sheet 3
DQD-2: U5.A23(IO_L8N_CC_LC_5) ; also on sheet 3
DQD-3: U5.B23(IO_L10N_5) ; also on sheet 3
DQD-4: U5.B20(IO_L2N_5) ; also on sheet 3
DQD-5: U5.B21(IO_L6N_5) ; also on sheet 3
DQD-6: U5.C25(IO_L20N_VREF_5) ; also on sheet 3
DQD-7: U5.D19(IO_L4N_VREF_5) ; also on sheet 3
DQD-8: U5.C22(IO_L14N_5) ; also on sheet 3
DQD-9: U5.C23(IO_L21N_5) ; also on sheet 3
DQD-10: U5.C24(IO_L16N_5) ; also on sheet 3
DQD-11: U5.D21(IO_L12N_VREF_5) ; also on sheet 3
ECE: R46.2 ; also on sheet 3
EXP_A_N0: U5.J1(IO_L4N_VREF_10) ; also on sheet 7
EXP_A_N1: U5.J4(IO_L2N_10) ; also on sheet 7
EXP_A_N2: U5.J6(IO_L1N_10) ; also on sheet 7
EXP_A_N3: U5.K1(IO_L10N_10) ; also on sheet 7
EXP_A_N4: U5.K2(IO_L7N_10) ; also on sheet 7
EXP_A_N5: U5.K4(IO_L6N_10) ; also on sheet 7
EXP_A_N6: U5.M1(IO_L11N_10) ; also on sheet 7
EXP_A_N7: U5.M3(IO_L12N_VREF_10) ; also on sheet 7
EXP_A_N8: U5.M5(IO_L13N_10) ; also on sheet 7
EXP_A_N9: U5.N2(IO_L14N_10) ; also on sheet 7
EXP_A_N10: U5.N4(IO_L15N_10) ; also on sheet 7
EXP_A_N11: U5.P2(IO_L16N_10) ; also on sheet 7
EXP_A_N12: U5.P4(IO_L18N_10) ; also on sheet 7
EXP_A_N13: U5.R1(IO_L22N_10) ; also on sheet 7
EXP_A_N14: U5.R3(IO_L20N_VREF_10) ; also on sheet 7
EXP_A_N15: U5.T3(IO_L26N_10) ; also on sheet 7
EXP_A_N16: U5.U2(IO_L28N_VREF_10) ; also on sheet 7
EXP_A_N17: U5.V1(IO_L30N_10) ; also on sheet 7
EXP_A_N18: U5.U4(IO_L29N_10) ; also on sheet 7
EXP_A_P0: U5.J2(IO_L4P_10) ; also on sheet 7
EXP_A_P1: U5.J5(IO_L2P_10) ; also on sheet 7
EXP_A_P2: U5.J7(IO_L1P_10) ; also on sheet 7
EXP_A_P3: U5.L1(IO_L10P_10) ; also on sheet 7
EXP_A_P4: U5.K3(IO_L7P_10) ; also on sheet 7
EXP_A_P5: U5.K5(IO_L6P_10) ; also on sheet 7
EXP_A_P6: U5.M2(IO_L11P_10) ; also on sheet 7
EXP_A_P7: U5.M4(IO_L12P_10) ; also on sheet 7
EXP_A_P8: U5.M6(IO_L13P_10) ; also on sheet 7
EXP_A_P9: U5.N3(IO_L14P_10) ; also on sheet 7
EXP_A_P10: U5.N5(IO_L15P_10) ; also on sheet 7
EXP_A_P11: U5.P3(IO_L16P_10) ; also on sheet 7
EXP_A_P12: U5.P5(IO_L18P_10) ; also on sheet 7
EXP_A_P13: U5.R2(IO_L22P_10) ; also on sheet 7
EXP_A_P14: U5.R4(IO_L20P_10) ; also on sheet 7
EXP_A_P15: U5.T4(IO_L26P_10) ; also on sheet 7
EXP_A_P16: U5.U3(IO_L28P_10) ; also on sheet 7
EXP_A_P17: U5.V2(IO_L30P_10) ; also on sheet 7
EXP_A_P18: U5.V4(IO_L29P_10) ; also on sheet 7
EXP_B_N0: U5.A8(IO_L3P_6) ; also on sheet 7
EXP_B_N1: U5.A6(IO_L6P_6) ; also on sheet 7
EXP_B_N2: U5.A4(IO_L15P_6) ; also on sheet 7
EXP_B_N3: U5.A3(IO_L14P_6) ; also on sheet 7
EXP_B_N4: U5.B7(IO_L11P_6) ; also on sheet 7
EXP_B_N5: U5.C5(IO_L12P_6) ; also on sheet 7
EXP_B_N6: U5.C4(IO_L16P_6) ; also on sheet 7
EXP_B_N7: U5.C2(IO_L20P_6) ; also on sheet 7
EXP_B_N8: U5.D8(IO_L4P_6) ; also on sheet 7
EXP_B_N9: U5.E7(IO_L17P_6) ; also on sheet 7
EXP_B_N10: U5.D3(IO_L22P_6) ; also on sheet 7
EXP_B_N11: U5.E6(IO_L18P_6) ; also on sheet 7
EXP_B_N12: U5.F4(IO_L27P_6) ; also on sheet 7
EXP_B_N13: U5.E1(IO_L26P_6) ; also on sheet 7
EXP_B_N14: U5.G6(IO_L23P_VRN_6) ; also on sheet 7
EXP_B_N15: U5.G4(IO_L28P_6) ; also on sheet 7
EXP_B_N16: U5.G2(IO_L30P_6) ; also on sheet 7
EXP_B_N17: U5.H4(IO_L31P_6) ; also on sheet 7
EXP_B_N18: U5.H2(IO_L32P_6) ; also on sheet 7
EXP_B_P0: U5.A7(IO_L3N_6) ; also on sheet 7
EXP_B_P1: U5.A5(IO_L6N_6) ; also on sheet 7
EXP_B_P2: U5.B4(IO_L15N_6) ; also on sheet 7
EXP_B_P3: U5.B3(IO_L14N_6) ; also on sheet 7
EXP_B_P4: U5.C7(IO_L11N_6) ; also on sheet 7
EXP_B_P5: U5.D5(IO_L12N_VREF_6) ; also on sheet 7
EXP_B_P6: U5.D4(IO_L16N_6) ; also on sheet 7
EXP_B_P7: U5.C1(IO_L20N_VREF_6) ; also on sheet 7
EXP_B_P8: U5.D7(IO_L4N_VREF_6) ; also on sheet 7
EXP_B_P9: U5.D6(IO_L17N_6) ; also on sheet 7
EXP_B_P10: U5.E4(IO_L22N_6) ; also on sheet 7
EXP_B_P11: U5.E5(IO_L18N_6) ; also on sheet 7
EXP_B_P12: U5.F3(IO_L27N_6) ; also on sheet 7
EXP_B_P13: U5.F1(IO_L26N_6) ; also on sheet 7
EXP_B_P14: U5.G5(IO_L23N_VRP_6) ; also on sheet 7
EXP_B_P15: U5.G3(IO_L28N_VREF_6) ; also on sheet 7
EXP_B_P16: U5.G1(IO_L30N_6) ; also on sheet 7
EXP_B_P17: U5.H3(IO_L31N_6) ; also on sheet 7
EXP_B_P18: U5.H1(IO_L32N_6) ; also on sheet 7
EXT_CLK_SELECT: R79.1 U5.AD7(IO_L23N_VRP_8)
FIFOADR0: U5.AC6(IO_L24P_CC_LC_8) ; also on sheet 4
FIFOADR1: U5.AB6(IO_L24N_CC_LC_8) ; also on sheet 4
FLAGA: U5.Y10(IO_L27P_8) ; also on sheet 4
FLAGB: U5.AA10(IO_L27N_8) ; also on sheet 4
FLAGC: U5.AC7(IO_L28P_8) ; also on sheet 4
FPGA_RESET: U5.AF8(IO_L25P_CC_LC_8) ; also on sheet 4
FSR: R27.2 ; also on sheet 3
IFCLK: U5.AC10(IO_L2P_GC_LC_4) ; also on sheet 4
LOAD_STATE: U5.AE7(IO_L23P_VRN_8) ; also on sheet 4
NDM: U5.AF21(IO_L30P_SM3_7) ; also on sheet 3
ORI+: U5.J26(IO_L4P_9) ; also on sheet 3
ORI-: U5.J25(IO_L4N_VREF_9) ; also on sheet 3
ORQ+: U5.H26(IO_L32P_5) ; also on sheet 3
ORQ-: U5.H25(IO_L32N_5) ; also on sheet 3
PDI: R44.2 ; also on sheet 3
PDQ: R45.2 ; also on sheet 3
PKTEND: U5.AE9(IO_L31N_8) ; also on sheet 4
PLL_CE: U5.C10(IO_L1N_6) U12.11(CE)
PLL_LD: U5.H5(IO_L29N_6) U12.30(Ftest/LD)
PLL_LE: U5.D10(IO_L1P_6) U12.10(LE)
PLL_SCLK: U5.G9(IO_L9N_CC_LC_6) U12.9(CLK)
PLL_SDATA: U5.G10(IO_L9P_CC_LC_6) U12.8(DATA)
PORen: R141.2 ; also on sheet 3
PROGRAMB: R85.2 U5.H15(PROG_B_0) U14.6(~{CF}) ; also on sheet 4
RD_N: U5.Y8(IO_L26N_8) ; also on sheet 4
SCL_FROM_CY: J15.8 J17.8 U8.13(SMBCLK) ; also on sheet 4
SCLK: U5.AE24(IO_L22N_7) ; also on sheet 3
SCS: U5.AF24(IO_L22P_7) ; also on sheet 3
SDA_FROM_CY: J15.6 J17.6 U8.12(SMBDAT) ; also on sheet 4
SDI: U5.AF22(IO_L30N_SM3_7) ; also on sheet 3
SDO: U5.AF18(IO_L31P_SM2_7) ; also on sheet 3
SLCS_N: U5.AB9(IO_L29N_8) ; also on sheet 4
SLOE: U5.AF9(IO_L31P_8) ; also on sheet 4
SLRD: U5.AE6(IO_L30P_8) ; also on sheet 4
SLWR: U5.AD6(IO_L30N_8) ; also on sheet 4
STATE0: U5.AD10(IO_L6N_GC_LC_4) ; also on sheet 4
STATE1: U5.AD17(IO_L7P_GC_VRN_LC_4) ; also on sheet 4
STATE2: U5.AD16(IO_L7N_GC_VRP_LC_4) ; also on sheet 4
STATE3: U5.AD12(IO_L8P_GC_CC_LC_4) ; also on sheet 4
TPM: R114.2 ; also on sheet 3
V_USI1: J15.2 J17.2 ; also on sheet 5
VCMO: J15.9 J17.9 ; also on sheet 3
WE_N: U5.AA8(IO_L26P_8) ; also on sheet 4
WSS: R140.2 ; also on sheet 3
B3/N16429333: C150.1 R74.1 T1.6
B3/N16429356: C151.1 R74.2 T1.4
B3/N16429929: C143.1 U12.36(VregDIG)
B3/N16433245: J11.3 U11.8(YA)
B3/N16433335: T1.2 U11.4(X2) U11.7(Y1)
B3/N16433810: Q1.1(BASE) R79.2 R80.2
B3/N16434585: C139.1 R66.1 R68.1 R69.1
B3/N16791454: Q1.3(COLLECTOR) U11.9(C2)
B3/N16792731: R75.1 R77.2 U11.2(XA)
B3/N16794028: R57.1 U11.3(X1)
B3/N16794697: R56.1 U11.6(Y2)
B3/N16935819: R66.2 R67.1 Y3.3(OUT)
B3/N18734025: C137.2 C138.2 C240.1 R65.2 Y3.4(VDD)
B3/N18774126: C140.2 U12.32(OSCin*)
B3/N18774266: C139.2 U12.31(OSCin)
B3/N18783537: C142.2 R70.1
B3/N18783684: C142.1 U12.28(VregPLL2)
B3/N18790993: C147.2 U12.26(VregPLL1)
B3/N18791141: C147.1 R71.1
B3/N18791292: R73.1 U12.25(FLout)
B3/N18791597: C146.2 C148.2 U12.23(Vtune) U12.24(CPout)
B3/N18791906: C148.1 R72.1 R73.2
B3/N18795674: C152.2 U12.21(Fout)
B3/N18796660: C152.1 R75.2 R76.2
B3/N18808450: C154.1 U12.17(VregVCO)
B3/N18808625: C154.2 R78.2
B3/N18808978: C155.2 U12.18(VrefVCO)
B3/N18815754: C149.2 U12.6(VregBUF)
B6/N16663533: J27.3 J28.3
B6/N16663537: J29.3 J30.3
B6/N16663541: J31.3 J32.3
B7/N16802160: R40.2 U5.G16(HSWAPEN_0)
B7/N16802193: C75.2 U5.H13(TDP_0) U8.6(D2+)
B7/N16802234: R31.2 U5.G14(CCLK_0)
B7/N16802239: R38.2 U5.W14(M2_0) U5.W15(M0_0) U5.Y15(M1_0)
B7/N16805252: R53.2 U5.AD11(IO_L8N_GC_CC_LC_4)
B7/N16805320: R53.1 Y2.3(OUT)
B7/N20455301: R83.3 U14.12(CLK)
B7/N20455532: R83.1 U14.9(CLKOUT)
B7/N21058732: R44.1 U5.AD19(IO_L25P_CC_SM7_LC_7)
B7/N21059382: R45.1 U5.AC19(IO_L25N_CC_SM7_LC_7)
B7/N21060033: R46.1 U5.AA19(IO_L26P_SM6_7)
B7/N21060685: R26.1 U5.AA20(IO_L26N_SM6_7)
B7/N21061338: R27.1 U5.Y17(IO_L27P_SM5_7)
B7/N21061992: R28.1 U5.AA17(IO_L27N_SM5_7)
B7/N21062647: R113.1 U5.AB20(IO_L28P_7)
B7/N21063303: R114.1 U5.AC20(IO_L28N_VREF_7)
B7/N21827542: R136.1 U25.7(Q+)
B7/N21827567: R134.1 U25.6(Q-)
B7/N21827581: J26.3 U25.2(D+)
B7/N21832116: U25.3(D-) U25.4(VBB)
B7/N21933562: R126.1 U8.9(A0)
B7/N22056748: R140.1 U5.AC26(IO_L9N_CC_LC_7)
B7/N22071512: R141.1 U5.AD26(IO_L11N_7)
N22420410: LD9.1(ANODE) R115.1
N22420411: LD5.1(ANODE) R51.1
N22420412: LD4.1(ANODE) R50.1
N22420413: LD1.1(ANODE) R47.1
N22420416: LD8.1(ANODE) R55.1
N22420419: LD6.1(ANODE) R52.1
N22420420: LD7.1(ANODE) R54.1
N22420421: LD3.1(ANODE) R49.1
N22420422: LD2.1(ANODE) R48.1

Not connected (* = marked no-connect by the designer): J15 10*; J17 10*; U5 A9(IO_L13P_6) A11(IO_L2N_GC_VRP_LC_3) A12(IO_L2P_GC_VRN_LC_3) A17(IO_L7N_GC_LC_3) A18(IO_L3N_5) AA18(IO_L21P_7) AA23(IO_L14N_7) AA24(IO_L8P_CC_LC_7)* AA26(IO_L10N_7) AB18(IO_L29N_SM4_7) AB21(IO_L24N_CC_LC_7) AB22(IO_L13N_7) AB23(IO_L14P_7) AB24(IO_L7P_7)* AB25(IO_L7N_7) AB26(IO_L10P_7) AC18(IO_L29P_SM4_7) AC21(IO_L24P_CC_LC_7) AC22(IO_L13P_7) AC23(IO_L16P_7) AC24(IO_L16N_7) AC25(IO_L9P_CC_LC_7) AD20(IO_L23N_VRP_7) AD21(IO_L32N_SM1_7) AD22(IO_L15P_7) AD23(IO_L15N_7) AE18(IO_L31N_SM2_7) AE20(IO_L23P_VRN_7) AE21(IO_L32P_SM1_7) AE23(IO_L19N_7) AF19(IO_L17P_7) B6(IO_L8P_CC_LC_6) B9(IO_L13N_6) B12(IO_L4N_GC_VREF_LC_3) B13(IO_L4P_GC_LC_3) B14(IO_L1N_GC_CC_LC_3) B15(IO_L1P_GC_CC_LC_3) B17(IO_L7P_GC_LC_3) B18(IO_L3P_5) C6(IO_L8N_CC_LC_6) C8(IO_L2N_6) C11(IO_L6P_D21_LC_1) C12(IO_L8N_GC_LC_3) C13(IO_L8P_GC_LC_3) C14(IO_L3N_GC_LC_3) C15(IO_L3P_GC_LC_3) C16(IO_L7N_D18_LC_1) C17(IO_L1P_5) C19(IO_L7P_5) D1(IO_L25N_CC_LC_6) D2(IO_L25P_CC_LC_6) D9(IO_L2P_6) D11(IO_L6N_D20_LC_1) D12(IO_L8N_D16_CC_LC_1) D13(IO_L4N_D24_VREF_LC_1) D14(IO_L4P_D25_LC_1) D15(IO_L5P_D23_LC_1) D16(IO_L7P_D19_LC_1) D17(IO_L1N_5) D18(IO_L7N_5) E2(IO_L24N_CC_LC_6) E3(IO_L24P_CC_LC_6) E9(IO_L7P_6) E10(IO_L5N_6) E13(IO_L8P_D17_CC_LC_1) E14(IO_L5N_D22_LC_1) E17(IO_L5P_5) E18(IO_L11N_5) F7(IO_L19P_6) F8(IO_L10P_6) F9(IO_L7N_6) F10(IO_L5P_6) F15(IO_L3N_D26_LC_1) F17(IO_L5N_5) F18(IO_L11P_5) G7(IO_L19N_6) G8(IO_L10N_6) G11(CS_B_0)* G20(IO_L22N_5) H6(IO_L29P_6) H7(IO_L21N_6) H8(IO_L21P_6) H12(RDWR_B_0)* H20(IO_L22P_5) K6(IO_L3N_10) K7(IO_L3P_10) K20(IO_L5N_9) L3(IO_L8N_CC_LC_10) L4(IO_L8P_CC_LC_10) L6(IO_L5N_10) L7(IO_L5P_10) L8(IO_L9N_CC_LC_10) L19(IO_L5P_9) M7(IO_L17N_10) M8(IO_L9P_CC_LC_10) M19(IO_L9P_CC_LC_9) N7(IO_L17P_10) N8(IO_L19N_10) N19(IO_L9N_CC_LC_9) P6(IO_L21N_10) P7(IO_L21P_10) P8(IO_L19P_10) P19(IO_L21N_9) P20(IO_L21P_9) R5(IO_L23N_VRP_10) R6(IO_L23P_VRN_10) R7(IO_L25N_CC_LC_10) R8(IO_L25P_CC_LC_10) R19(IO_L25N_CC_LC_9) R20(IO_L25P_CC_LC_9) T1(IO_L24N_CC_LC_10) T6(IO_L27N_10) T7(IO_L27P_10) T8(IO_L31P_10) T19(IO_L31N_9) U1(IO_L24P_CC_LC_10) U5(IO_L32N_10) U6(IO_L32P_10) U7(IO_L31N_10) U20(IO_L31P_9) U21(IO_L29N_9) U22(IO_L29P_9) U23(IO_L27P_9) V20(IO_L5N_7) V21(IO_L1P_7) V22(IO_L1N_7) V23(IO_L27N_9) W13(PWRDWN_B_0)* W19(IO_L18N_7) W20(IO_L5P_7) W21(IO_L3P_7) W22(IO_L3N_7) W23(IO_L4P_7) W24(IO_L4N_VREF_7) W25(IO_L2P_7) W26(IO_L2N_7) Y14(DOUT_BUSY_0)* Y18(IO_L21N_7) Y19(IO_L18P_7) Y20(IO_L20P_7) Y21(IO_L20N_VREF_7) Y22(IO_L12P_7) Y23(IO_L12N_VREF_7) Y24(IO_L8N_CC_LC_7)* Y25(IO_L6P_7) Y26(IO_L6N_7)*; U6 2* 4* 6*; U7 2* 4* 6*; U8 1(NC1)* 3(NC2)* 4(NC3)*; U12 2(NC-1)* 4(NC-2)* 5(NC-3)* 7(NC-4)* 12(NC-5)* 13(NC-6)* 14(NC-7)* 15(NC-8)* 29(NC-9)* 35(NC-10)* 39(NC-11)*; U14 1(DNC-1)* 3(DNC-2)* 5(BUSY)* 10(~{CEO})* 14(DNC-3)* 16(DNC-4)* 18(DNC-5)* 25(~{EN_XSEL})* 26(RV_SEL0)* 27(RV_SEL1)* 29(D1)* 32(D2)* 33(D3)* 35(DNC-6)* 37(DNC-7)* 39(DNC-8)* 40(DNC-9)* 41(DNC-10)* 42(DNC-11)* 43(D4)* 44(D5)* 47(D6)* 48(D7)*; U25 1(NC)*; Y2 1(OE); Y3 1(NC)*

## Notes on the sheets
sheet 8
- Assuming Transmission line...
  Populate R5 and R6
- Loop Filter
  Place Close to LMX2531
  Surrond in Copper Pour
- EXTERNAL
  CLOCK
  INPUT
sheet 9
- BANK 3 - 2.5V LVDS (GCLK)
- BANK 9 - 2.5 V I/O (LVDS)
- BANK 5 - 2.5 V I/O (LVDS)
- BANK 7 - 1.8 V I/O
- BANK 8 - 3.3 V I/O
- BANK 6 - 2.5V I/O
sheet 10
- TEST HEADERS
- SLAVE SERIAL
- MASTER SERIAL
- FIT R43 IF
  CONFIG
  FLASH NOT
  INSTALLED
- JTAG HEADER
- TEST INPUTS
- BANK 10 - 2.5V I/O
- Place C75 and C76 close to LM95233
- BANK 2 - 2.5V I/O
- TEMP SENSOR
- DO NOT FIT V4
  CONFIG FLASH IF
  CYPRESS USB
  CONTROLLER IS
  INSTALLED
- BANK 1 - 3.3 V I/O
- SLAVE
  SERIAL
- MASTER
  SERIAL
- BANK 4 - 3.3 V I/O
- USI-1 HEADER #1
- 100MHZ FPGA CLOCK REF
- USI-1 HEADER #2
- ACTIVE LOW
sheet 11
- BANK0
- BANK1
- BANK2
- BANK #
- BANK SUPPLY
- INTERFACE
- 1
  2
  3
  4
  5
  6
  7
  8
  9
  10
- 2V5IO
  2V5IO
  2V5IO
  3V3IO
  2V5IO
  3V3IO
  1V8IO
  3V3IO
  2V5IO
  2V5IO
- Clock Generator
  Test Headers, Temp. Sensor
  Cypress, LEDs, 100MHz Oscillator
  ADC DCLK (LVDS)
  ADC Q-Channel (LVDS)
  USI-1 Header
  ADC Control
  Cypress, LEDs
  ADC I-Channel (LVDS)
  Logic Analyzer Header
- BANK3
- BANK4
- BANK5
- BANK6
- BANK7
- BANK8
- BANK9
- BANK10
sheet 12
- Impedance test connectors
- 50 Ohms
- 100 Ohms
